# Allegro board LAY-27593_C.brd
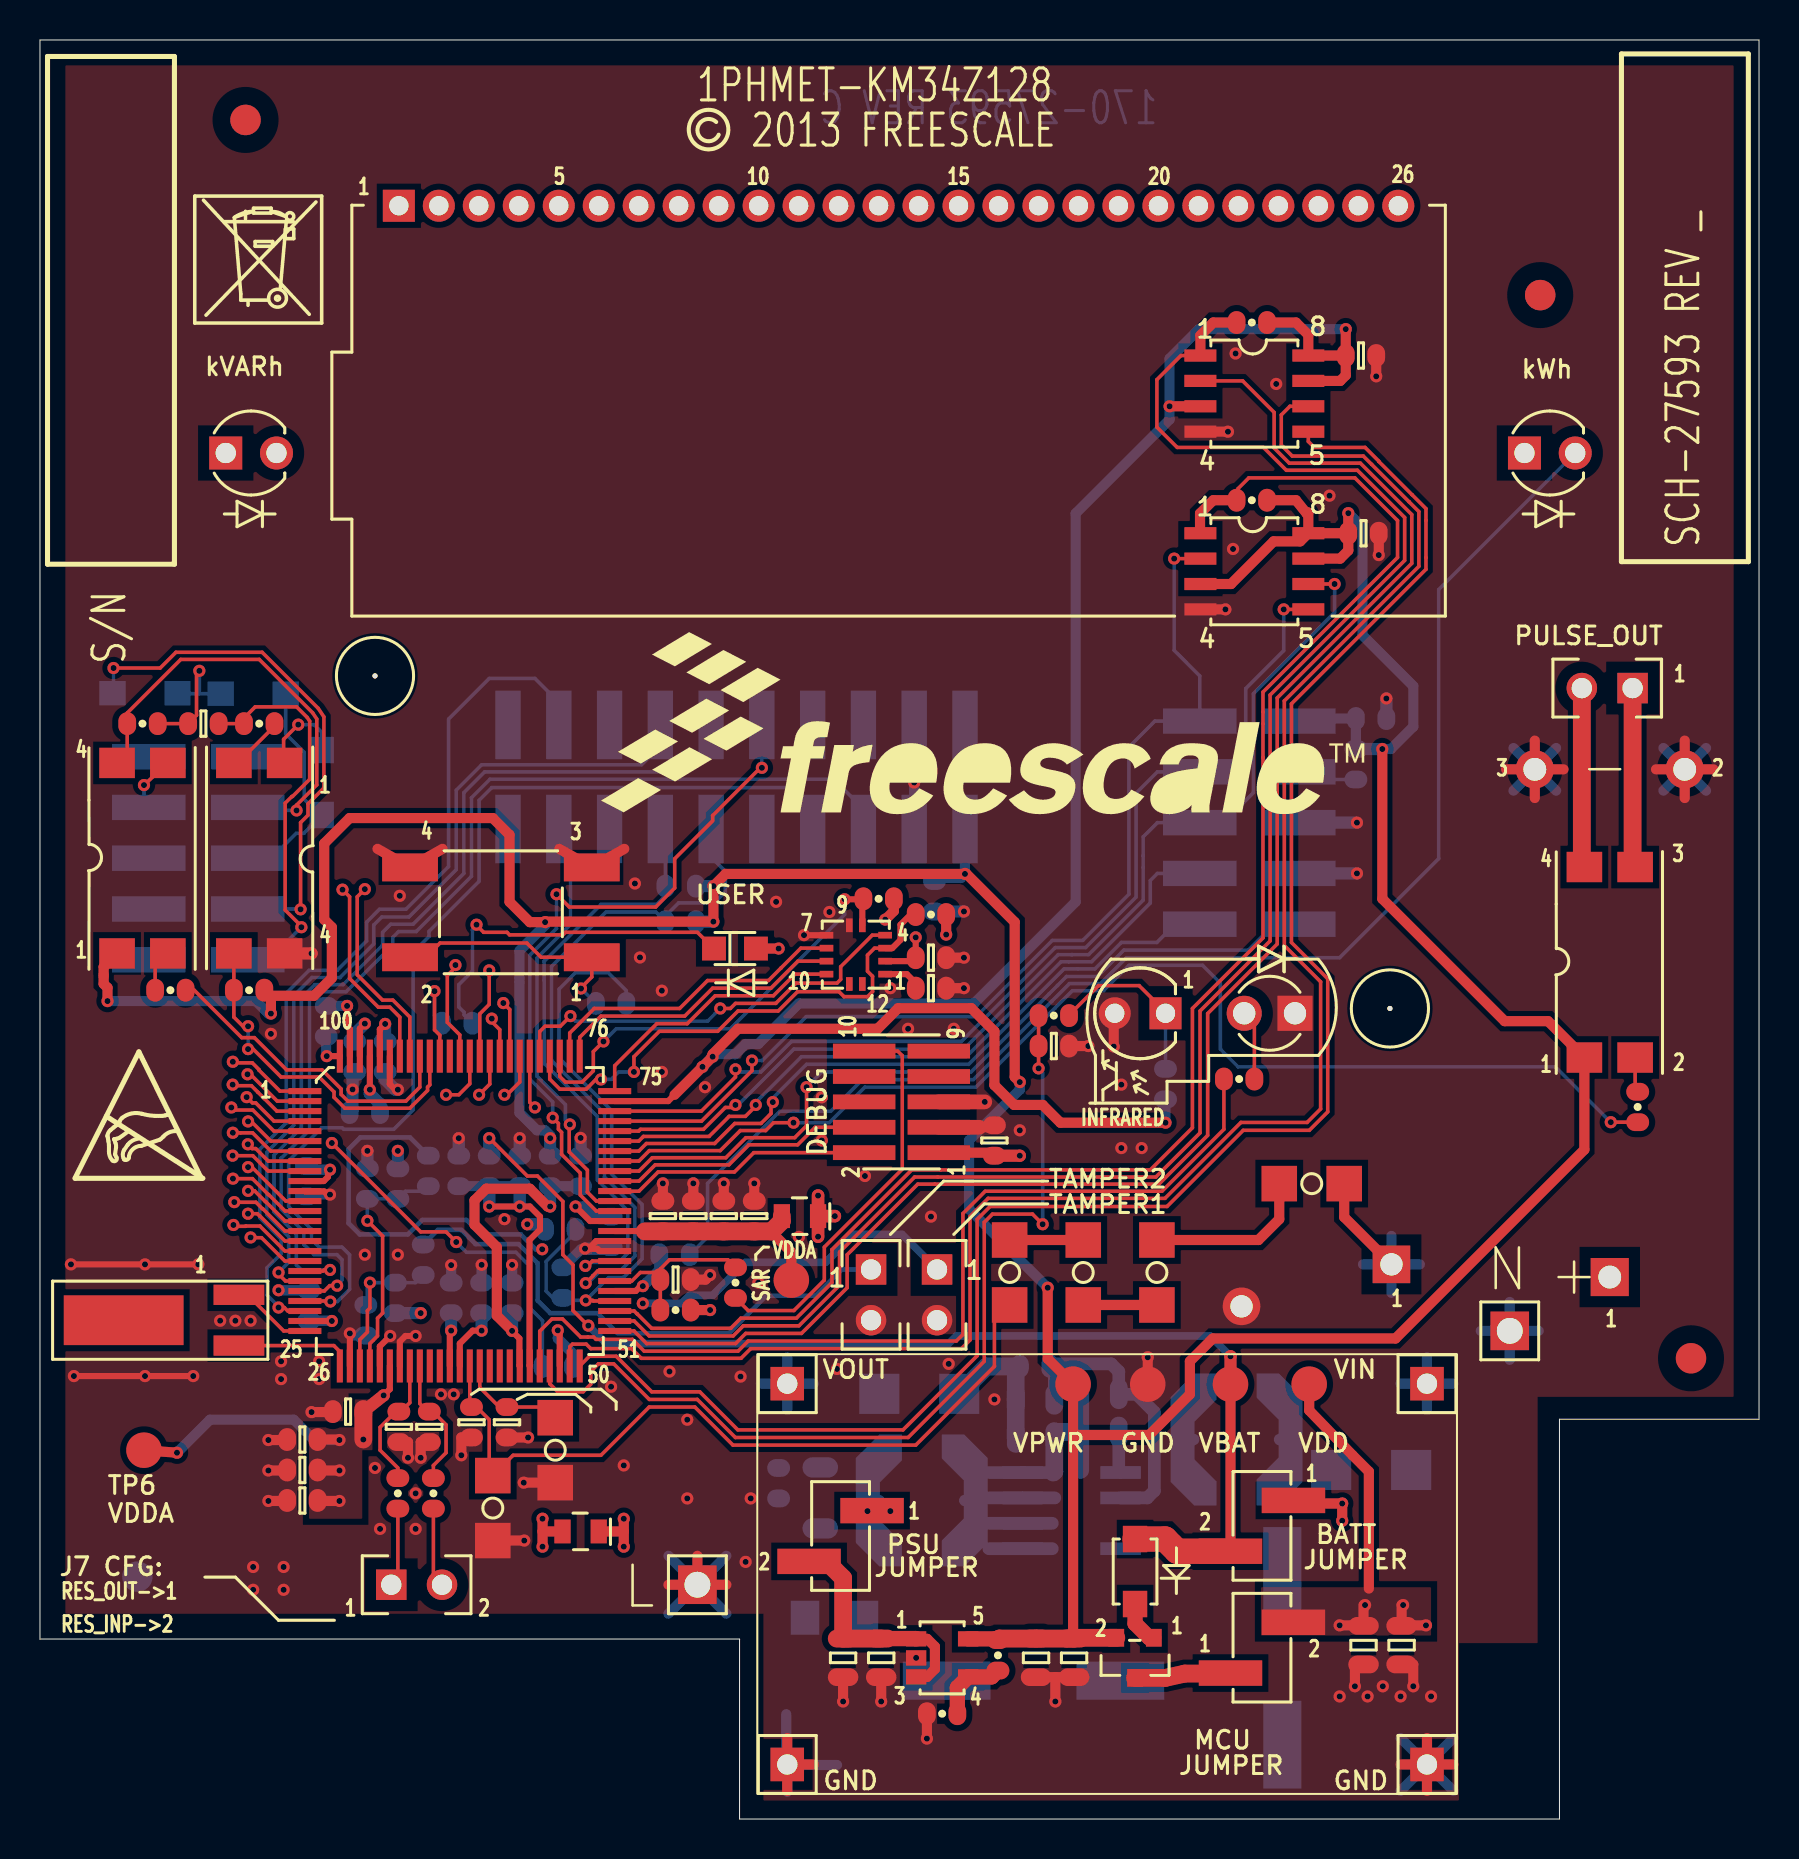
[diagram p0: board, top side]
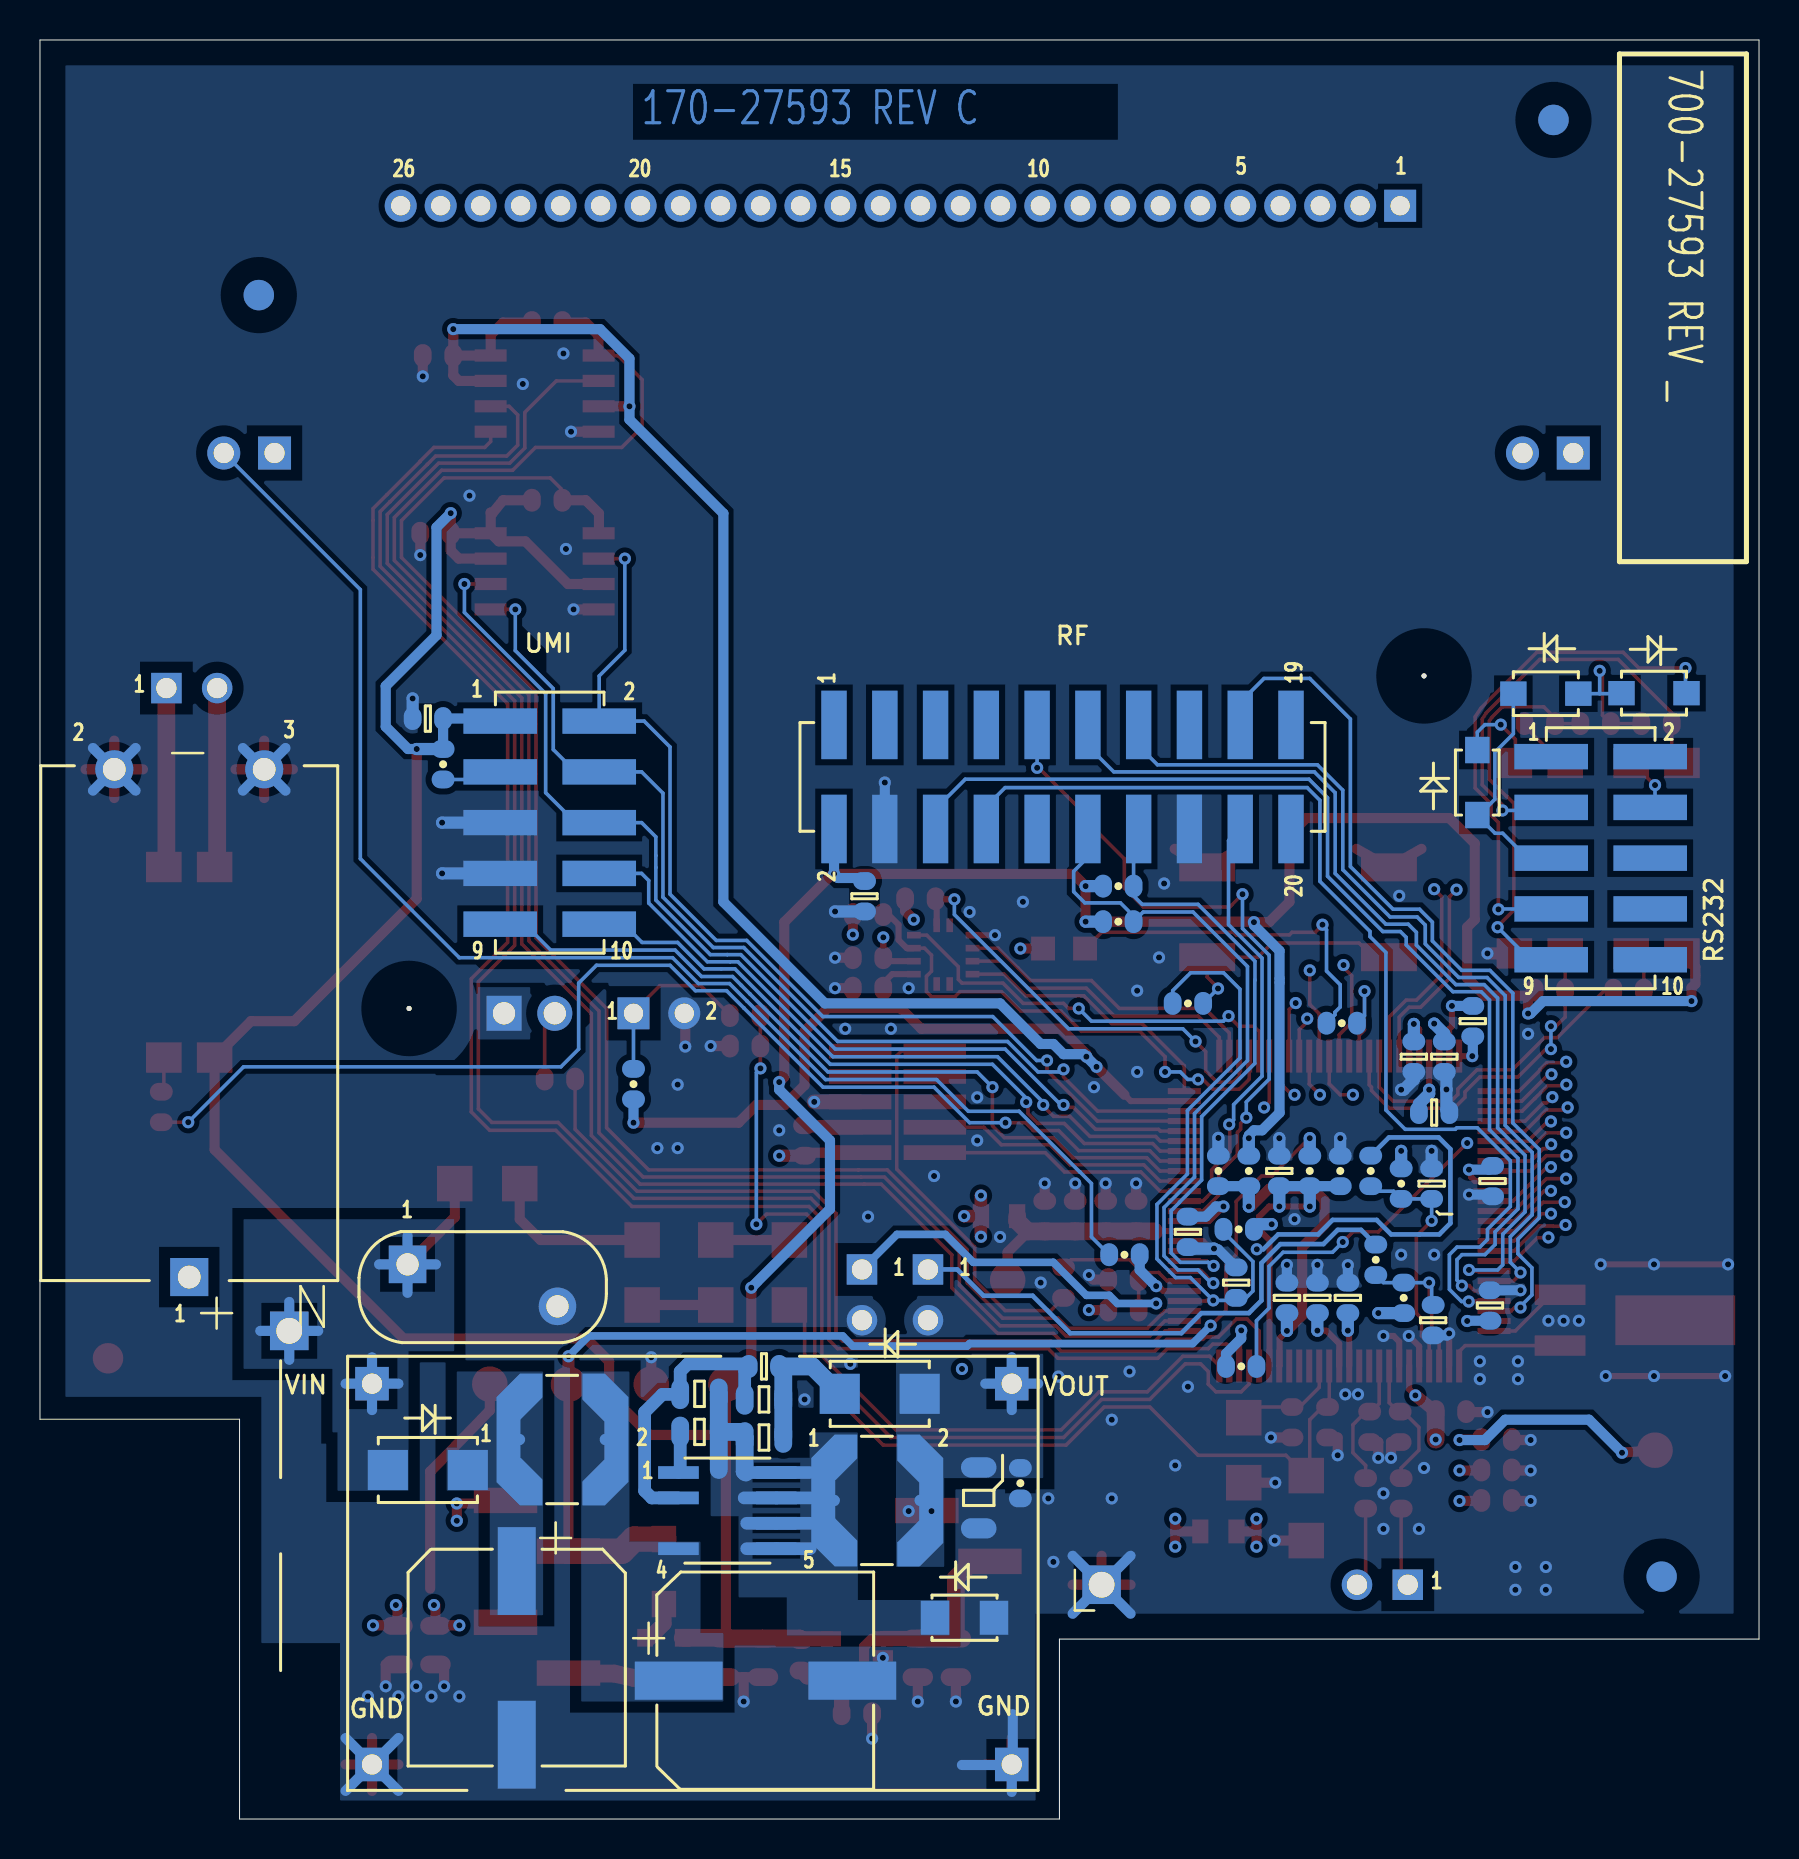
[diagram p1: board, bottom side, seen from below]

Outline 86 x 89 mm; copper layers: TOP, L2_GND, L3_PWR, BOTTOM. Coordinates in mm from the lower left corner of the outline.
Outline path: 0,89 86,89 86,20 76.02,20 76.02,0 35,0 35,9 0,9 0,89

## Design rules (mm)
net group PWR: nets KVARH_LED KWH_LED N7676044 N7742135 N7743508 N7798929 N7799438 N7845653 N7881250 PWR_MSR SAR_VDDA VBAT VBAT_MSR VCAP1 VCAP2 VLL1 VLL2 VLL3 VPWR VREF VREFH VREFL

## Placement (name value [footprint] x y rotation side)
BT200  ER142503PT  [BT25P4_14P5_TH]  78.53 27.11 90 bottom
C1  0.1UF  [CC0603_OV]  66.09 73.21 0 top
C2  0.1UF  [CC0603_OV]  66.21 64.32 0 top
C3  2.2uF  [CC0603_OV]  8.17 54.8 180 top
C4  0.1UF  [CC0603_OV]  44.57 43.09 0 top
C5  0.1UF  [CC0603_OV]  44.57 41.57 0 top
C6  2200PF  [CC0603_OV]  50.72 38.67 0 top
C7  0.1UF  [CC0603_OV]  47.75 33.95 90 top
C8  0.1UF  [CC0603_OV]  31.16 30.16 90 top
C9  1uF  [CC0603_OV]  32.69 30.16 90 top
C10  1uF  [CC0603_OV]  34.21 30.16 90 top
C11  1uF  [CC0603_OV]  35.73 30.16 90 top
C12  0.1UF  [CC0603_OV]  31.8 26.99 0 top
C13  0.1UF  [CC0603_OV]  15.41 20.38 180 top
C14  0.015 UF  [CC0603_OV]  21.59 19.85 270 top
C15  0.015 UF  [CC0603_OV]  23.36 19.85 270 top
C16  0.1UF  [CC0603_OV]  17.95 19.62 270 top
C17  0.1UF  [CC0603_OV]  19.48 19.62 270 top
C18  1uF  [CC0603_OV]  13.13 18.99 180 top
C19  1uF  [CC0603_OV]  13.13 17.46 180 top
C20  1uF  [CC0603_OV]  13.13 15.94 180 top
C21  10UF  [CC0805_OV]  66.21 8.7 270 top
C22  10UF  [CC0805_OV]  68.12 8.7 270 top
C23  10UF  [CC0805_OV]  40.18 8.06 270 top
C24  10UF  [CC0805_OV]  42.08 8.06 270 top
C25  10UF  [CC0805_OV]  49.83 8.06 270 top
C26  10UF  [CC0805_OV]  51.74 8.06 270 top
C200  0.1UF  [CC0603_OV]  66.59 55.05 0 bottom
C201  0.1UF  [CC0603_OV]  44.75 46.16 270 bottom
C202  0.1UF  [CC0603_OV]  14.32 39.91 90 bottom
C203  0.1UF  [CC0603_OV]  17.27 38.14 270 bottom
C204  0.1UF  [CC0603_OV]  15.74 38.14 270 bottom
C205  0.1UF  [CC0603_OV]  16.25 35.34 180 bottom
C206  0.1UF  [CC0603_OV]  24 32.42 90 bottom
C207  0.1UF  [CC0603_OV]  13.33 31.91 270 bottom
C208  2200PF  [CC0603_OV]  16.38 31.79 90 bottom
C209  0.1UF  [CC0603_OV]  28.57 29.37 270 bottom
C210  0.1UF  [CC0603_OV]  26.16 26.83 90 bottom
C211  0.1UF  [CC0603_OV]  23.62 26.07 90 bottom
C212  0.1UF  [CC0603_OV]  22.09 26.07 90 bottom
C213  0.1UF  [CC0603_OV]  20.57 26.07 90 bottom
C214  0.1UF  [CC0603_OV]  13.46 25.69 90 bottom
C215  2200PF  [CC0603_OV]  16.3 24.95 270 bottom
C216  4.7uF  [CC0603_OV]  49.78 22.64 0 bottom
C217  0.1uF  [CC0805_OV]  53.01 19.37 180 bottom
C218  10uF  [CC0805_OV]  49.78 19.09 0 bottom
C219  100UF  [CC1206_OV]  39.04 16.06 270 bottom
C220  4.7uF  [CCE10_3X10_3]  62.15 8.06 270 bottom
C221  4.7uF  [CCE10_3X10_3]  49.7 6.92 180 bottom
D1  WP7104LSRD  [LED_2_3P85]  9.29 68.34 0 top
D2  WP7104LSRD  [LED_2_3P85]  74.27 68.34 0 top
D3  HSMS-C170  [HSMX-C170]  34.77 43.55 180 top
D4  TSAL4400  [LED2_100_3_TH]  62.78 40.31 180 top
D5  MMSD4148T1G  [SOD-123]  54.78 12.38 270 top
D6  BAT54CLT1  [SOT23_A]  54.78 8.06 180 top
D200  MMSD4148T1G  [SOD-123]  5.25 56.32 180 bottom
D201  MMSD4148T1G  [SOD-123]  10.66 56.3 0 bottom
D202  MMSD4148T1G  [SOD-123]  14.09 51.85 90 bottom
D203  MRA4007T3G  [CASE403D_02]  43.99 21.27 180 bottom
D204  MRA4007T3G  [CASE403D_02]  66.59 17.46 0 bottom
D205  ES1JL  [DIODE2_2P9X1P9]  39.75 10.07 180 bottom
DS1  LCD MODULE  [LCD26_2MM_54P15X20MM_TH]  17.95 80.71 0 top
J1  HDR 1X2  [HDR102]  79.68 56.58 270 top
J2  HDR 2X5  [CON_2X5_FTS_SM]  43.1 35.88 90 top
J3  HDR 1X2  [HDR102]  41.58 27.49 0 top
J4  HDR 1X2  [HDR102]  44.88 27.49 0 top
J5  HDR_1X2  [HDR102_STAG_SM]  61.13 14.67 180 top
J6  HDR_1X2  [HDR102_STAG_SM]  40.05 14.16 180 top
J7  HDR 1X2  [HDR102]  17.57 11.72 90 top
J8  HDR_1X2  [HDR102_STAG_SM]  61.13 8.57 0 top
J200  CON_2X10  [CON2X10F_SMT_SSW]  34.84 52.13 90 bottom
J201  HDR_2X5  [HDR205_SM]  60.5 49.85 180 bottom
J202  HDR_2X5  [HDR205_SM]  7.92 48.07 180 bottom
JP1  HDR 1X1  [HDR101]  37.38 21.78 0 top
JP2  HDR 1X1  [HDR101]  69.39 21.78 0 top
JP3  HDR 1X1  [HDR101]  32.89 11.72 0 top
JP4  HDR 1X1  [HDR101]  37.38 2.73 180 top
JP5  HDR 1X1  [HDR101]  69.39 2.73 0 top
JP6  HDR 1X1  [HDR101]  73.53 24.42 0 top
L1  1uH  [IND_2012]  38.02 30.16 180 top
L2  1uH  [IND_2012]  27.05 14.39 180 top
L200  1500uH  [IND_LPS6225]  59.86 18.99 180 bottom
L201  820uH  [IND_LPS6225]  44.12 15.94 180 bottom
NOREF  -  []  76.02 0 0 top
NOREF#2  -  [unnamed#2]  10.28 85 0 top
NOREF#3  -  []  16.76 57.19 0 top
NOREF#4  -  []  -309.96 -251.52 0 top
NOREF#5  -  []  85.47 62.9 90 top
NOREF#6  -  [unnamed#2]  67.53 40.55 0 top
NOREF#7  -  []  86 20 0 top
NOREF#8  -  []  284.4 -45.78 0 top
NOREF#9  -  []  1.77 32.05 0 top
NOREF#10  -  []  -285.83 274.26 0 top
NOREF#11  -  []  6.73 62.77 90 top
NOREF#12  -  [unnamed#2]  75.05 76.24 0 top
NOREF#13  -  []  7.74 74.84 0 top
NOREF#14  -  []  86 89 0 top
NOREF#15  -  []  33.45 52.39 0 top
NOREF#16  -  []  67.53 40.55 0 top
NOREF#17  -  [unnamed#2]  82.6 23.05 0 top
NOREF#18  -  []  35 0 0 top
NOREF#19  -  []  0 89 0 top
NOREF#20  -  []  35 0 0 top
NOREF#21  -  []  86 89 0 top
NOREF#22  -  []  76.83 85.25 0 top
NOREF#23  -  []  -8.08 -35.62 0 top
NOREF#24  -  []  16.76 57.19 0 top
NOREF#25  -  []  0 9 0 top
NOREF#26  -  []  28.06 50.96 0 top
NOREF#27  -  []  16.76 57.19 0 top
NOREF#28  -  [unnamed#2]  16.76 57.19 0 top
NOREF#29  -  []  67.53 40.55 0 top
NOREF#30  -  []  77.09 83.73 180 bottom
NOREF#31  -  [unnamed#2]  10.28 85 180 bottom
NOREF#32  -  []  6.98 88.3 270 bottom
NOREF#33  -  [unnamed#2]  4.87 12.13 180 bottom
NOREF#34  -  [unnamed#2]  75.05 76.24 180 bottom
Q1  OP506B  [PHTRANS_4P19MM]  56.31 40.31 180 top
R1  10K  [RC0603_OV]  60.63 74.87 180 top
R2  10K  [RC0603_OV]  60.63 65.98 180 top
R3  4.7K  [RC0603_OV]  5.13 54.8 0 top
R4  470  [RC0603_OV]  10.97 54.8 180 top
R5  4.7K  [RC0603_OV]  41.96 46.04 180 top
R6  4.7K  [RC0603_OV]  44.57 45.25 180 top
R7  390.0  [RC0603_OV]  6.52 41.46 180 top
R8  1.0K  [RC0603_OV]  10.46 41.46 180 top
R9  1.0K  [RC0603_OV]  50.72 40.19 0 top
R10  680  [RC0603_OV]  59.99 37.02 0 top
R11  390.0  [RC0603_OV]  79.93 35.62 90 top
R12  150K  [RC_MELF_0204]  63.62 31.79 180 top
R13  150K  [RC_MELF_0204]  48.51 27.34 270 top
R14  150K  [RC_MELF_0204]  52.19 27.34 90 top
R15  150K  [RC_MELF_0204]  55.88 27.34 270 top
R16  820  [RC0603_OV]  34.79 26.83 90 top
R17  4.7K  [RC0603_OV]  31.8 25.46 180 top
R18  390  [RC_MELF_0204]  25.78 18.45 270 top
R19  22  [RC0603_OV]  17.9 16.29 90 top
R20  22  [RC0603_OV]  19.68 16.29 90 top
R21  390  [RC_MELF_0204]  22.65 15.56 270 top
R23  45.3K  [RC0603_OV]  47.93 8.19 270 top
R24  23.7K  [RC0603_OV]  45.13 5.27 180 top
R200  0  [RC0603_OV]  65.83 52.77 270 bottom
R201  4.7K  [RC0603_OV]  32.05 46.67 180 bottom
R202  4.7K  [RC0603_OV]  32.05 44.89 180 bottom
R203  10K  [RC0603_OV]  28.57 40.8 180 bottom
R204  2.0K  [RC0603_OV]  20.87 39.81 0 bottom
R205  10K  [RC0603_OV]  56.31 36.77 90 bottom
R206  330K  [RC0603_OV]  27.05 32.42 90 bottom
R207  47K  [RC0603_OV]  25.52 32.42 270 bottom
R208  4.7M  [RC0603_OV]  22.48 32.42 270 bottom
R209  1.6M  [RC0603_OV]  20.95 32.42 90 bottom
R210  10K  [RC0603_OV]  19.43 32.42 90 bottom
R211  4.7M  [RC0603_OV]  17.9 31.79 270 bottom
R212  330K  [RC0603_OV]  26.03 29.5 0 bottom
R213  390.0  [RC0603_OV]  31.75 28.23 0 bottom
R214  10K  [RC0603_OV]  19.17 27.98 90 bottom
R215  4.7M  [RC0603_OV]  17.78 26.07 90 bottom
R216  390.0  [RC0603_OV]  25.9 22.64 180 bottom
R217  2.0K  [RC0805_OV]  53.01 21.27 180 bottom
R218  3.0K  [RC0805_OV]  49.78 20.99 0 bottom
R219  1.6K  [RC0603_OV]  36.95 16.8 270 bottom
RV200  S10K250E2  [VARISTOR_12X5P2MM]  67.61 27.75 180 bottom
SW1  TL3301AF160QG  [SW4_PB_ESW_SM_P177]  23.06 45.36 270 top
TP1  70 MIL  [TESTPOINT_70MIL]  37.59 26.96 0 top
TP2  70 MIL  [TESTPOINT_70MIL]  51.69 21.75 0 top
TP3  70 MIL  [TESTPOINT_70MIL]  55.42 21.75 0 top
TP4  70 MIL  [TESTPOINT_70MIL]  59.56 21.75 0 top
TP5  70 MIL  [TESTPOINT_70MIL]  63.5 21.75 0 top
TP6  70 MIL  [TESTPOINT_70MIL]  5.2 18.45 0 top
U1  CAT25040VE  [SO8_1P27_4X5]  60.75 71.31 0 top
U2  W25X10CLSN  [SO8_1P27_4X5]  60.75 62.42 0 top
U3  SFH6106-4  [SOP4_2P54_6P8X4P8]  10.97 48.07 270 top
U4  SFH6106-4  [SOP4_2P54_6P8X4P8]  5.13 48.07 90 top
U5  MMA8491Q  [QFN12_0P65_3X3_A]  40.81 43.24 180 top
U6  SFH6106-4  [SOP4_2P54_6P8X4P8]  78.53 42.86 90 top
U7  PKM34Z128CLL5  [LQFP100_0P5_14X14]  21 30.42 0 top
U8  SPX3819M5-L  [SOT23-5_A]  45.13 8.06 0 top
U200  LNK302DN  [SO8_1P27_3P9X4P9]  51.61 15.43 180 bottom
Y1  32.768KHz  [XTL2_ECS_SM]  5.38 24.95 0 top

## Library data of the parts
BT200 = BAT_ER142503PT
C1-C5 C7-C13 C16-C26 C200-C207 C209-C214 C216 = CAP_NP: tolerance: 10%
C6 C14 C15 C208 C215 = CAP_NP: tolerance: 5%
C217 C218 = CAP_NP
C219 = CAP_NP: tolerance: 20%
C220 C221 = CAP_POL: tolerance: 20%
D1-D4 = LED
D5 D200-D205 = DIODE
D6 = DUALDIODE_CC_SOT23
DS1 = LCD_MODULE_26P
J1 J3-J8 = CONN_HDR_2X1
J2 J201 J202 = CONN_HDR_5X2
J200 = CONN_HDR_10X2
JP1-JP6 = CONN_HDR_1X1
L1 L2 = INDUCTOR: tolerance: 25%
L200 L201 = IND: tolerance: 20%
Q1 = PT12_PHTRANS_2P
R1-R3 R5 R6 R10 R16 R17 R201-R205 R207 R210 R214 = RES: tolerance: 5%
R4 R7-R9 R11-R15 R19 R20 R23 R24 R200 R206 R208 R209 R211-R213 R215-R219 = RES: tolerance: 1%
R18 R21 = RES: tolerance: 0.1%
RV200 = VARISTOR
SW1 = SW_PB_ESW
TP1-TP6 = Test pad: User Part Number: 510-75218; Tolerance: TOLERANCE
U1 = CAT25040VE_8P
U2 = W25X10C_8P
U3 U4 U6 = SFH6106_4P
U5 = PMA8491_QFN_12P_EPX
U7 = PKM34Z128_LQFP_100P
U8 = SPX3819M5_5P
U200 = LNK302DN_8P
Y1 = XTAL

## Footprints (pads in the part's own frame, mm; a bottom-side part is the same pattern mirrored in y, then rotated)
BT25P4_14P5_TH
  rect 1.905x1.905 hole 1.143: 1(0,0)
  round 1.905 hole 1.143: 2(25.4,3.75) 3(25.4,-3.75)
CASE403D_02
  rect 2.007x2.007 smd: A(2,0) C(-2,0)
CC0603_OV
  oval 0.889x1.143 smd: 1(-0.762,0) 2(0.762,0)
CC0805_OV
  oval 0.889x1.524 smd: 1(-0.965,0) 2(0.965,0)
CC1206_OV
  oval 1.016x1.778 smd: 1(-1.524,0) 2(1.524,0)
CCE10_3X10_3
  rect 4.394x1.905 smd: 1(-4.343,0) 2(4.343,0)
CON2X10F_SMT_SSW
  rect 3.429x1.27 smd: 1(2.603,11.43) 2(-2.603,11.43) 3(2.603,8.89) 4(-2.603,8.89) 5(2.603,6.35) 6(-2.603,6.35) 7(2.603,3.81) 8(-2.603,3.81) 9(2.603,1.27) 10(-2.603,1.27) 11(2.603,-1.27) 12(-2.603,-1.27) 13(2.603,-3.81) 14(-2.603,-3.81) 15(2.603,-6.35) 16(-2.603,-6.35) 17(2.603,-8.89) 18(-2.603,-8.89) 19(2.603,-11.43) 20(-2.603,-11.43)
CON_2X5_FTS_SM
  rect 0.737x3.124 smd: 1(-2.54,-1.867) 2(-2.54,1.867) 3(-1.27,-1.867) 4(-1.27,1.867) 5(0,-1.867) 6(0,1.867) 7(1.27,-1.867) 8(1.27,1.867) 9(2.54,-1.867) 10(2.54,1.867)
DIODE2_2P9X1P9
  rect 1.422x1.702 smd: A(1.475,0) C(-1.475,0)
HDR101
  rect 1.93x1.93 hole 1.295: 1(0,0)
HDR102
  rect 1.524x1.524 hole 1.016: 1(0,0)
  round 1.524 hole 1.016: 2(0,-2.54)
HDR102_STAG_SM
  rect 3.175x1.27 smd: 1(-1.575,-1.27) 2(1.575,1.27)
HDR205_SM
  rect 3.683x1.27 smd: 1(-2.477,5.08) 2(2.477,5.08) 3(-2.477,2.54) 4(2.477,2.54) 5(-2.477,0) 6(2.477,0) 7(-2.477,-2.54) 8(2.477,-2.54) 9(-2.477,-5.08) 10(2.477,-5.08)
HSMX-C170
  rect 1.194x1.194 smd: A(-1.05,0) C(1.05,0)
IND_2012
  rect 0.813x1.194 smd: 1(-0.906,0) 2(0.906,0)
IND_LPS6225
  custom 0.575x0.575 smd: 1(-2.15,0) 2(2.15,0)
LCD26_2MM_54P15X20MM_TH
  rect 1.6x1.6 hole 0.965: 1(0,0)
  round 1.6 hole 0.965: 2(2,0) 3(4,0) 4(6,0) 5(8,0) 6(10,0) 7(12,0) 8(14,0) 9(16,0) 10(18,0) 11(20,0) 12(22,0) 13(24,0) 14(26,0) 15(28,0) 16(30,0) 17(32,0) 18(34,0) 19(36,0) 20(38,0) 21(40,0) 22(42,0) 23(44,0) 24(46,0) 25(48,0) 26(50,0)
LED2_100_3_TH
  round 1.753 hole 1.118: A(2.54,0)
  rect 1.753x1.753 hole 1.118: C(0,0)
LED_2_3P85
  rect 1.651x1.651 hole 1.016: A(0,0)
  round 1.651 hole 1.016: C(2.54,0)
LQFP100_0P5_14X14
  rect 1.651x0.305 smd: 1(-7.75,6) 2(-7.75,5.5) 3(-7.75,5) 4(-7.75,4.5) 5(-7.75,4) 6(-7.75,3.5) 7(-7.75,3) 8(-7.75,2.5) 9(-7.75,2) 10(-7.75,1.5) 11(-7.75,1) 12(-7.75,0.5) 13(-7.75,0) 14(-7.75,-0.5) 15(-7.75,-1) 16(-7.75,-1.5) 17(-7.75,-2) 18(-7.75,-2.5) 19(-7.75,-3) 20(-7.75,-3.5) 21(-7.75,-4) 22(-7.75,-4.5) 23(-7.75,-5) 24(-7.75,-5.5) 25(-7.75,-6) 51(7.75,-6) 52(7.75,-5.5) 53(7.75,-5) 54(7.75,-4.5) 55(7.75,-4) 56(7.75,-3.5) 57(7.75,-3) 58(7.75,-2.5) 59(7.75,-2) 60(7.75,-1.5) 61(7.75,-1) 62(7.75,-0.5) 63(7.75,0) 64(7.75,0.5) 65(7.75,1) 66(7.75,1.5) 67(7.75,2) 68(7.75,2.5) 69(7.75,3) 70(7.75,3.5) 71(7.75,4) 72(7.75,4.5) 73(7.75,5) 74(7.75,5.5) 75(7.75,6)
  rect 0.305x1.651 smd: 26(-6,-7.75) 27(-5.5,-7.75) 28(-5,-7.75) 29(-4.5,-7.75) 30(-4,-7.75) 31(-3.5,-7.75) 32(-3,-7.75) 33(-2.5,-7.75) 34(-2,-7.75) 35(-1.5,-7.75) 36(-1,-7.75) 37(-0.5,-7.75) 38(0,-7.75) 39(0.5,-7.75) 40(1,-7.75) 41(1.5,-7.75) 42(2,-7.75) 43(2.5,-7.75) 44(3,-7.75) 45(3.5,-7.75) 46(4,-7.75) 47(4.5,-7.75) 48(5,-7.75) 49(5.5,-7.75) 50(6,-7.75) 76(6,7.75) 77(5.5,7.75) 78(5,7.75) 79(4.5,7.75) 80(4,7.75) 81(3.5,7.75) 82(3,7.75) 83(2.5,7.75) 84(2,7.75) 85(1.5,7.75) 86(1,7.75) 87(0.5,7.75) 88(0,7.75) 89(-0.5,7.75) 90(-1,7.75) 91(-1.5,7.75) 92(-2,7.75) 93(-2.5,7.75) 94(-3,7.75) 95(-3.5,7.75) 96(-4,7.75) 97(-4.5,7.75) 98(-5,7.75) 99(-5.5,7.75) 100(-6,7.75)
PHTRANS_4P19MM
  rect 1.6x1.6 hole 0.965: 1(0,0)
  round 1.6 hole 0.965: 2(2.54,0)
QFN12_0P65_3X3_A
  rect 0.686x0.33 smd: 1(-1.468,0.975) 2(-1.468,0.325) 3(-1.468,-0.325) 4(-1.468,-0.975) 7(1.468,-0.975) 8(1.468,-0.325) 9(1.468,0.325) 10(1.468,0.975)
  rect 0.33x0.686 smd: 5(-0.325,-1.468) 6(0.325,-1.468) 11(0.325,1.468) 12(-0.325,1.468)
RC0603_OV
  oval 0.889x1.143 smd: 1(-0.762,0) 2(0.762,0)
RC0805_OV
  oval 0.889x1.524 smd: 1(-0.965,0) 2(0.965,0)
RC_MELF_0204
  rect 1.778x1.778 smd: 1(-1.625,0) 2(1.625,0)
SO8_1P27_3P9X4P9
  rect 2.032x0.635 smd: 1(-2.45,1.905) 2(-2.45,0.635) 4(-2.45,-1.905) 5(2.45,-1.905) 6(2.45,-0.635) 7(2.45,0.635) 8(2.45,1.905)
SO8_1P27_4X5
  rect 1.6x0.61 smd: 1(-2.7,1.905) 2(-2.7,0.635) 3(-2.7,-0.635) 4(-2.7,-1.905) 5(2.7,-1.905) 6(2.7,-0.635) 7(2.7,0.635) 8(2.7,1.905)
SOD-123
  rect 1.321x1.219 smd: A(-1.626,0) C(1.626,0)
SOP4_2P54_6P8X4P8
  rect 1.52x1.78 smd: 1(-4.765,1.27) 2(-4.765,-1.27) 3(4.765,-1.27) 4(4.765,1.27)
SOT23-5_A
  rect 1.016x0.762 smd: 1(-1.3,0.95) 2(-1.3,0) 3(-1.3,-0.95) 4(1.3,-0.95) 5(1.3,0.95)
SOT23_A
  rect 0.787x0.889 smd: 1(-0.94,-1.003) 2(0.94,-1.003) 3(0,1.003)
SW4_PB_ESW_SM_P177
  rect 1.397x2.794 smd: 1(2.248,4.547) 2(2.248,-4.547) 3(-2.248,4.547) 4(-2.248,-4.547)
TESTPOINT_70MIL
  round 1.778 smd: 1(0,0)
unnamed#2
  round 1.524 smd: (0,0)
VARISTOR_12X5P2MM
  rect 1.88x1.88 hole 1.118: 1(0,0)
  round 1.88 hole 1.118: 2(7.5,-2.1)
XTL2_ECS_SM
  rect 5.994x2.489 smd: (-1.194,0)
  rect 2.54x1.016 smd: 1(4.572,1.27) 2(4.572,-1.27)

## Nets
GND: BT200.2(-VE1) BT200.3(-VE2) C1.2 C2.2 C4.2 C5.2 C6.2 C7.2 C8.2 C9.2 C10.2 C11.2 C12.2 C13.2 C14.2 C15.2 C16.2 C17.2 C18.2 C19.2 C20.2 C21.2 C22.2 C23.2 C24.2 C25.2 C26.2 C200.2 C201.2 C203.2 C204.2 C205.2 C206.2 C207.2 C208.2 C209.2 C210.2 C211.2 C212.2 C213.2 C214.2 C215.2 C219.2 C220.2 C221.2 D4.C(CATHODE) D205.A(ANODE) J2.3(A2) J2.5(A3) J3.2 J4.2 J200.4 J200.16 J201.5(A3) J201.7(A4) JP3.1 JP4.1 JP5.1 Q1.2(EMITTER) R18.2 R21.2 R24.2 R206.2 R209.2 R219.2 RV200.2 SW1.3(B1) SW1.4(B2) TP3.1(PIN1) U1.4(VSS) U2.4(GND) U3.4(EMITTER) U5.6(GND#6) U5.7(GND#7) U7.11(VSS1) U7.27(VSS2) U7.30(TAMPER0) U7.32(VSSA) U7.59(VSS3) U7.60(SAR_VSSA) U7.95(VSS4) U8.2(GND)
VBAT: D5.A(ANODE) J5.2 R208.1 TP4.1(PIN1)
VBAT_MSR: C206.1 R208.2 R209.1 U7.45(PTC6/AD1/SCI0_CTS/QT1)
VDD: C4.1 C7.1 C21.1 C22.1 C207.1 C209.1 C214.1 D1.A(ANODE) D2.A(ANODE) D3.A(ANODE) J2.1(A1) J8.2 L1.1 L2.1 R5.1 R6.1 R17.1 R211.1 R212.1 R215.1 TP5.1(PIN1) U5.2(VDD) U7.10(VDD1) U7.24(VBAT) U7.62(VDD2)
VDDA: C13.1 C18.1 C19.1 C20.1 L2.2 TP6.1(PIN1) U7.31(VDDA)
VIN: D204.A(ANODE) JP2.1 JP6.1 R12.1 RV200.1
/PULSE_OUT: R11.1 U7.68(PTF1/LCD0/AD8/QT0/PXBAR_OUT6)
/RESET: C12.1 R16.2 R17.2 U7.56(PTE1/R\E\S\E\T\)
COM1: DS1.23 U7.84(PTH1/LCD16)
COM2: DS1.24 U7.83(PTH0/LCD15)
COM3: DS1.25 U7.82(PTG7/LCD14)
COM4: DS1.26 U7.81(PTG6/LCD13/LLWU_P0/LPTIM2)
EEPROM_SS: R1.2 U1.1(C\S\) U7.52(PTD5/AD4/LPTIM2/QT0/SCI3_CTS)
FLASH_SS: R2.2 U2.1(C\S\) U7.53(PTD6/AD5/LPTIM1/CMP1OUT/SCI3_RT)
I2C0_SCL: R5.2 U5.5(SCL) U7.78(PTG3/LCD10/SPI0_SCK/I2C0_SCL)
I2C0_SDA: R6.2 U5.3(SDA) U7.79(PTG4/LCD11/SPI0_MOSI/I2C0_SDA)
I2C1_SCL: J200.14 R201.2 U7.58(PTE3/XTAL1/EWM_OUT/AFE_CLK/I2C1)
I2C1_SDA: J200.12 R202.2 U7.57(PTE2/EXTAL1/EWM_IN/PXBAR_IN6/I2)
KVARH_LED: R216.1 U7.48(PTD1/SCI1_TXD/S\P\I\0\_\S\S\/PX)
KWH_LED: R213.1 U7.55(PTE0/I2C0_SDA/PXBAR_OUT4/SCI3_T)
LCD1: DS1.1 U7.18(PTB7/LCD38/AFE_CLK)
LCD2: DS1.2 U7.17(PTB6/LCD37/CMP1P0)
LCD3: DS1.3 U7.16(PTB5/LCD36)
LCD4: DS1.4 U7.15(PTB4/LCD35)
LCD5: DS1.5 U7.14(PTB3/LCD34)
LCD6: DS1.6 U7.13(PTB2/LCD33)
LCD7: DS1.7 U7.12(PTB1/LCD32)
LCD8: DS1.8 U7.9(PTB0/LCD31)
LCD9: DS1.9 U7.8(PTA7/LCD30/PXBAR_OUT0)
LCD10: DS1.10 U7.7(PTA6/LCD29/PXBAR_IN0/LLWU_P14)
LCD11: DS1.11 U7.6(PTA5/LCD28/CMP0OUT)
LCD12: DS1.12 U7.5(PTA4/LCD27/LLWU_P15/N\M\I\)
LCD13: DS1.13 U7.4(PTA3/LCD26)
LCD14: DS1.14 U7.3(PTA2/LCD25)
LCD15: DS1.15 U7.2(PTA1/LCD24)
LCD16: DS1.16 U7.1(PTA0/LCD23)
LCD17: DS1.17 U7.94(PTI3/LCD22)
LCD18: DS1.18 U7.93(PTI2/LCD21)
LCD19: DS1.19 U7.88(PTH5/LCD20)
LCD20: DS1.20 U7.87(PTH4/LCD19)
LCD21: DS1.21 U7.86(PTH3/LCD18)
LCD22: DS1.22 U7.85(PTH2/LCD17)
MMA_EN: U5.4(EN) U7.80(PTG5/LCD12/SPI0_MISO/LPTIM1)
MMA_XOUT: U5.10(XOUT) U7.75(PTG0/LCD7/QT1/LPTIM2)
MMA_YOUT: U5.9(YOUT) U7.76(PTG1/LCD8/AD10/LLWU_P2/LPTIM0)
MMA_ZOUT: U5.8(ZOUT) U7.77(PTG2/LCD9/AD11/S\P\I\0\_\S\S\/L)
PWR_MSR: C211.1 R206.1 R207.2 U7.44(PTC5/AD0/SCI0_RTS/LLWU_P12)
RES_INP: J7.2 R20.1
RES_OUT: J7.1 R19.1
RF_CTRL: J200.18 U7.64(PTE5/QT3/SCI2_RTS/EWM_OUT/LLWU_)
RF_IO: J200.17 U7.23(PTC4/LCD43)
RF_RST: J200.9 U7.63(PTE4/LPTIM0/SCI2_CTS/EWM_IN)
SAR_VDDA: C8.1 C9.1 C10.1 C11.1 L1.2 TP1.1(PIN1) U7.61(SAR_VDDA)
SCI0_RX: C6.1 R9.1 U7.47(PTD0/CMP0P0/SCI0_RXD/PXBAR_IN2/)
SCI0_TX: R10.1 U7.46(PTC7/AD2/SCI0_TXD/PXBAR_OUT2)
SCI1_RX: R8.2 U3.3(COLLECTOR) U7.91(PTI0/CMP0P5/SCI1_RXD/PXBAR_IN8/)
SCI1_TX: R7.1 U7.92(PTI1/SCI1_TXD/PXBAR_OUT8/SPI1_M)
SCI3_CTS: J200.13 U7.20(PTC1/LCD40/CMP1P1/SCI3_CTS)
SCI3_RTS: J200.11 U7.19(PTC0/LCD39/SCI3_RTS/PXBAR_IN1)
SCI3_RX: J200.8 U7.22(PTC3/LCD42/CMP0P3/SCI3_RXD/LLWU)
SCI3_TX: J200.6 U7.21(PTC2/LCD41/SCI3_TXD/PXBAR_OUT1)
SDADM0: C17.1 R20.2 U7.34(SDADM0)
SDADM2: C15.1 R18.1 U7.40(SDADM2/CMP1P3)
SDADP0: C16.1 R19.2 U7.33(SDADP0)
SDADP2: C14.1 R13.2 R21.1 U7.39(SDADP2/CMP1P2)
SPI0_MISO: U1.2(SO) U7.51(PTD4/AD3/SCI1_RTS/SPI0_MISO/LLW)
SPI0_MOSI: U1.5(SI) U7.50(PTD3/SCI1_CTS/SPI0_MOSI)
SPI0_SCK: U1.6(SCK) U7.49(PTD2/CMP0P1/SCI1_RXD/SPI0_SCK/P)
SPI1_MISO: J201.2(B1) U2.2(DO/IO1) U7.72(PTF5/LCD4/SPI1_MISO/I2C1_SCL/LL)
SPI1_MOSI: J201.4(B2) U2.5(DI/IO0) U7.73(PTF6/LCD5/SPI1_MOSI/I2C1_SDA/LL)
SPI1_SCK: J201.6(B3) U2.6(CLK) U7.71(PTF4/LCD3/SPI1_SCK/LPTIM0/SCI0_)
SWD_CLK: J2.4(B2) U7.66(PTE7/AD6/PXBAR_OUT5/SCI2_TXD/SW)
SWD_IO: J2.2(B1) U7.65(PTE6/CMP0P2/PXBAR_IN5/SCI2_RXD/)
SWD_RESET: J2.10(B5) R16.1
TAMPER1: C208.1 R210.1 R211.2 U7.29(TAMPER1)
TAMPER2: C215.1 R214.1 R215.2 U7.28(TAMPER2)
UMI_INT: J201.9(A5) U7.67(PTF0/AD7/RTCCLKOUT/QT2/CMP0OUT)
UMI_RST: J201.10(B5) U7.69(PTF2/LCD1/AD9/CMP1OUT/RTCCLKOUT)
UMI_SS: J201.8(B4) U7.70(PTF3/LCD2/S\P\I\1\_\S\S\/LPTIM1)
USER_BTN: C210.1 R203.1 R212.2 U7.54(PTD7/CMP0P4/I2C0_SCL/PXBAR_IN4/)
USER_LED: R204.1 U7.90(PTH7/SCI1_RTS/SPI1_SCK/PXBAR_OU)
VAUX: C1.1 R1.1 R205.1 U1.3(W\P\) U1.7(H\O\L\D\) U1.8(VCC) U7.74(PTF7/LCD6/QT2/CLKOUT)
VCAP1: C202.1 U7.100(VCAP1)
VCAP2: C202.2 U7.99(VCAP2)
VLL1: C204.1 U7.98(VLL1)
VLL2: C205.1 U7.97(VLL2)
VLL3: C203.1 U7.96(VLL3)
VOUT: C219.1 D203.A(ANODE) J6.1 JP1.1 L201.2 R219.1
VPWR: C2.1 C25.1 C26.1 C200.1 C201.1 D6.2(A2) J200.2 J201.1(A1) R2.1 R8.1 R23.1 R200.1 R201.1 R202.1 R207.1 TP2.1(PIN1) U2.3(W\P\) U2.7(H\O\L\D\) U2.8(VCC) U4.1(ANODE) U6.1(ANODE) U8.5(VOUT)
VREF: U7.41(VREF)
VREFH: C213.1 U7.37(VREFH)
VREFL: C212.1 U7.38(VREFL)
N7254025: J201.3(A2) R200.2
N7311373: Q1.1(COLLECTOR) R9.2 R205.2
N7313274: D4.A(ANODE) R10.2
N7314056: D2.C(CATHODE) R213.2
N7314060: D1.C(CATHODE) R216.2
N7317031: J1.1 U6.3(COLLECTOR)
N7317123: J202.3(A2) R3.1 U4.4(EMITTER)
N7317135: R4.1 U3.2(CATHODE)
N7317139: C3.2 D200.A(ANODE) D201.A(ANODE) R3.2
N7317159: C3.1 J202.9(A5) R4.2
N7317195: D200.C(CATHODE) J202.7(A4)
N7317203: D201.C(CATHODE) D202.A(ANODE) J202.5(A3)
N7317219: J202.4(B2) U4.3(COLLECTOR)
N7317435: R11.2 U6.2(CATHODE)
N7330976: J1.2 U6.4(EMITTER)
N7332359: R7.2 U4.2(CATHODE)
N7333527: D202.C(CATHODE) U3.1(ANODE)
N7413835: C5.1 U5.1(BYP)
N7432331: R13.1 R14.2
N7432681: R14.1 R15.2
N7432685: R12.2 R15.1
N7470913: C217.2 C218.2 D205.C(CATHODE) L201.1 R217.2 U200.5(S1) U200.6(S2) U200.7(S3) U200.8(S4)
N7471025: C220.1 D204.C(CATHODE) L200.1
N7471045: C221.1 L200.2 U200.4(D)
N7471057: C217.1 U200.1(BP)
N7471061: C216.2 R217.1 R218.2 U200.2(FB)
N7471069: C216.1 C218.1 D203.C(CATHODE) R218.1
N7676044: C23.1 C24.1 J6.2 U8.1(VIN) U8.3(EN)
N7706869: U7.25(XTAL32K) Y1.1
N7742135: D5.C(CATHODE) D6.1(A1)
N7743508: R23.2 R24.1 U8.4(ADJ)
N7798929: J4.1 R210.2
N7799438: J3.1 R214.2
N7817781: U7.26(EXTAL32K) Y1.2
N7845653: D6.3(C) J8.1
N7881250: BT200.1(+VE) J5.1
N8061225: D3.C(CATHODE) R204.2
N8098939: R203.2 SW1.1(A1) SW1.2(A2)

Pads without a net: J2 6 7 8 9; J200 1 3 5 7 10 15 19 20; J202 1 2 6 8 10; U5 11 12; U7 35 36 42 43 89

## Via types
v1: diameter 0.61, hole 0.305, TOP to BOTTOM, 262 vias

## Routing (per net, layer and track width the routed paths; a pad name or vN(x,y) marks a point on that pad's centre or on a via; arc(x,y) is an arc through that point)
GND: length 192.5
  TOP w0.305: v1(17.52,24.17) 17,23.65 U7.30 ; U7.95 17.5,36.76 17.78,36.49 v1(17.9,36.49) ; U7.27 v1(15.5,24.29) ; U7.32 18,23.88 18.28,24.17 v1(18.79,24.17) ; U7.11 13.27,31.4 14.21,31.4 14.37,31.24 v1(14.51,31.24) ; v1(1.55,27.75) v1(5.25,27.75) v1(7.92,27.75) ; U7.59 27.99,28.42 27.88,28.52 27.28,28.52 v1(27.27,28.54) 27.45,28.54 27.83,28.92 U7.60 ; v1(7.67,22.16) v1(5.25,22.16) v1(1.7,22.16) ; U5.7 v1(38.22,44.22)
  TOP w0.508: v1(13.59,20.36) 14.65,20.36 C13.2 ; 50.8,7.1 C26.2 ; 50.8,7.1 C25.2 ; 50.8,7.1 v1(50.8,5.88) ; C9.2 v1(32.69,31.8) ; C8.2 v1(31.16,31.8) ; 46.99,34.61 47.65,34.61 C7.2 ; U1.4 v1(59.43,69.4) ; C1.2 v1(66.85,72.17) ; 80.85,52.51 BT200.2 ; BT200.2 82.28,53.95 ; BT200.2 82.28,51.08 ; BT200.2 83.72,52.51 ; v1(24.2,16.83) R18.2 ; C6.2 v1(52.45,38.67) 52.45,38.64 ; R24.2 v1(44.37,4.02) ; JP5.1 70.71,2.73 ; JP5.1 69.39,4.05 ; JP5.1 69.39,1.41 ; JP5.1 68.07,2.73 ; v1(66.98,63.23) C2.2 ; v1(11.43,17.44) 12.37,17.44 C19.2 ; v1(53.72,38.64) 53.72,40.31 Q1.2 ; v1(11.43,15.91) 12.37,15.91 C20.2 ; v1(33.52,27.21) 33.3,26.99 C12.2 ; v1(65.78,6.64) 65.78,7.73 C21.2 ; v1(68.7,6.64) 68.7,7.73 C22.2 ; 37.38,1.41 JP4.1 ; JP4.1 38.71,2.73 ; JP4.1 37.38,4.05 ; TP3.1 v1(55.42,23.1) ; BT200.3 76.22,52.51 ; BT200.3 74.78,51.08 ; BT200.3 73.35,52.51 ; BT200.3 74.78,53.95 ; C24.2 v1(42.08,5.88) ; v1(18.41,18.07) 18.41,18.86 C16.2 ; v1(24.42,19.09) C15.2 ; C23.2 v1(40.18,5.88) ; U2.4 v1(59.31,60.51) ; v1(19.05,18.07) 19.05,18.86 C17.2 ; JP3.1 32.89,13.17 ; JP3.1 34.34,11.72 ; JP3.1 31.44,11.72 ; C5.2 v1(46.22,41.57) ; 16.89,48.53 SW1.4 20.14,48.53 ; C18.2 12.37,18.96 v1(11.43,18.96) ; C11.2 v1(35.73,31.8) ; 29.23,48.53 SW1.3 25.98,48.53 ; v1(24.23,13.93) R21.2 ; C4.2 v1(46.22,43.09) ; C10.2 v1(34.21,31.8) ; v1(21.08,18.2) 21.08,19.09 C14.2
  TOP w0.61: U3.4 v1(13.59,43.3)
  TOP w0.737: 46.99,34.61 J2.3 ; J2.5 v1(47.27,35.88)
  L2_GND w0.508: 74.78,51.08 BT200.3 ; BT200.3 76.22,52.51 ; BT200.3 73.35,52.51 ; BT200.3 74.78,53.95 ; JP3.1 34.34,11.72 ; JP3.1 32.89,13.17 ; JP3.1 31.44,11.72 ; JP4.1 37.79,2.32 39.62,2.32 ; JP4.1 37.21,2.91 37.21,4.74 ; JP4.1 38.63,3.97 ; 62.78,38.09 D4.C 62.78,42.25 ; 82.28,51.08 BT200.2 ; BT200.2 80.85,52.51 ; BT200.2 82.28,53.95 ; BT200.2 83.72,52.51 ; 68.07,2.73 JP5.1 ; JP5.1 69.39,4.05 ; JP5.1 70.71,2.73
  BOTTOM w0.508: v1(11.93,26.45) C214.2 ; J200.4 v1(43.73,51.85) ; JP3.1 34.34,13.17 ; JP3.1 34.34,10.27 ; JP3.1 31.44,10.27 ; JP3.1 31.44,13.17 ; 81.22,53.58 BT200.2 ; BT200.2 83.35,51.45 ; BT200.2 83.35,53.58 ; BT200.2 81.22,51.45 ; JP5.1 70.71,4.05 ; JP5.1 70.71,1.41 ; JP5.1 68.07,1.41 ; JP5.1 68.07,4.05 ; v1(14.51,31.24) 13.42,31.24 C207.2 ; JP4.1 37.41,2.7 39.87,2.7 ; JP4.1 37.38,1.36 ; JP4.1 37.33,2.78 37.33,5.24 ; 73.72,53.58 BT200.3 ; BT200.3 75.85,51.45 ; BT200.3 75.85,53.58 ; BT200.3 73.72,51.45 ; v1(27.27,28.54) 27.23,28.49 27.06,28.49 C210.2 ; v1(15.5,24.29) 15.6,24.19 C215.2 ; C212.2 v1(22.09,27.72) ; C211.2 v1(23.62,27.72) ; C213.2 v1(20.57,27.71)
  BOTTOM w0.61: C205.2 15.64,35.49 v1(15.64,36.5) 15.64,37.27 C204.2 ; R209.2 v1(20.95,34.06) ; C203.2 17.27,36.99 17.78,36.49 v1(17.9,36.49) ; C200.2 v1(67.36,56.06) ; J201.7 v1(65.88,47.31) ; C209.2 28.49,28.54 v1(27.27,28.54) ; v1(46.22,45.4) C201.2 ; C208.2 v1(16.38,33.42) ; J201.5 v1(65.88,49.85) ; R206.2 v1(27.05,34.07) ; C206.2 v1(24,34.06)
  vias: v1(9.01,24.93) v1(9.78,24.93) v1(10.54,24.93) v1(10.66,12.61) v1(10.66,11.47) v1(11.55,39.28) v1(12.06,22.9) v1(12.06,22.01) v1(12.19,12.61) v1(12.19,11.47) v1(13.97,22.9) v1(13.97,22.01) v1(16.25,28.23) v1(16.76,17.56) v1(17.01,14.51) v1(17.9,28.23) v1(18,46.19) v1(18.79,16.29) v1(18.79,14.51) v1(20.06,21.25) v1(20.7,21.25) v1(23.24,30.01) v1(28.57,21.63) v1(29.21,17.69) v1(29.76,46.8) v1(30.02,43.1) v1(31.11,41.44) v1(31.11,37.37) v1(31.49,22.39) v1(32.38,19.98) v1(32.38,16.04) v1(33.27,36.61) v1(35.05,22.13) v1(35.3,12.86) v1(35.56,16.04) v1(35.94,26.83) v1(36.83,45.88) v1(37.97,29.12) v1(39.11,36.1) v1(39.11,33.95) v1(39.49,45.38) v1(39.87,22.52) v1(41.27,32.17) v1(42.54,41.57) v1(43.43,39.53) v1(43.83,8.06) v1(44.57,30.14) v1(45.46,22.77) v1(45.72,39.53) v1(47.75,20.99) v1(49.02,34.45) v1(54.1,36.74) v1(54.1,33.56) v1(55.11,33.56) v1(59.69,63.54) v1(59.81,73.32) v1(61.85,71.79) v1(64.51,66.2) v1(65.02,6.13) v1(66.42,6.13) v1(67.18,6.64) v1(68.07,6.13) v1(69.59,6.13)
VBAT: length 60.6
  TOP w0.178: v1(22.48,34.06) 22.49,34.06 24.38,32.17 24.89,32.17 26.16,30.9 26.16,28.23 26.67,27.72 26.67,25.44 27.42,24.68 v1(27.43,24.68)
  TOP w0.508: J5.2 TP4.1
  TOP w0.61: TP4.1 v1(59.56,23.15)
  TOP w1.27: D5.A 56.28,14.01 56.89,13.4 J5.2
  BOTTOM w0.381: v1(59.56,23.15) 58.54,24.17 45.84,24.17 45.34,23.66 39.62,23.66 39.49,23.79 28.33,23.79 v1(27.43,24.68)
  BOTTOM w0.61: R208.1 v1(22.48,34.06)
VBAT_MSR: length 15.5
  TOP w0.305: U7.45 24.49,22.68 24.49,28.97 25.02,29.49 25.02,30.14 24.51,30.64 v1(24,30.64) v1(22.48,30.64)
  BOTTOM w0.508: R209.1 R208.2 C206.1
  BOTTOM w0.61: R208.2 v1(22.48,30.64) ; C206.1 v1(24,30.64)
VDD: length 76.9
  TOP w0.305: U7.10 14.2,31.91 14.41,32.13 14.41,32.38 v1(14.51,32.48) ; v1(26.79,30.64) 27.52,29.92 U7.62 ; v1(43.81,44.11) C4.1 43.64,42.92 U5.2 ; U7.24 v1(14.6,24.92)
  TOP w0.508: v1(42.29,44.99) 42.72,45.43 R5.1 ; 68.12,9.69 v1(69.34,9.69) ; 68.12,9.69 68.12,10.7 v1(68.2,10.7) ; 68.12,9.69 C22.1 ; 66.21,9.69 v1(65.02,9.69) ; 66.21,9.69 66.21,10.7 ; 66.21,9.69 C21.1 ; TP5.1 63.5,20.44 65.67,18.2 66.48,17.38 66.48,11.53 ; L2.1 29.21,14.39 ; 29.21,14.39 v1(29.21,15.02) ; 29.21,14.39 v1(29.21,13.63) ; J2.1 47.6,33.34 C7.1 ; D3.A v1(36.95,43.55) ; R6.1 v1(45.34,44.25) ; R17.1 v1(33.52,25.46)
  TOP w0.61: C7.1 v1(49.02,33.18)
  TOP w0.635: L1.1 v1(38.93,29.13) ; L1.1 v1(38.93,31.19) ; L1.1 v1(39.76,30.16)
  L3_PWR w0.508: D1.A 9.29,60.21 12.06,57.44 12.06,41.92 ; 72.96,68.34 D2.A ; D2.A 74.27,67.03 ; D2.A 74.27,69.65 ; 12.85,43.8 12.82,43.83
  BOTTOM w0.508: v1(26.79,30.64) 27.17,30.64 27.68,30.14 C209.1 ; v1(14.51,32.48) 13.52,32.48 C207.1 ; C214.1 14.59,24.93 v1(14.6,24.92)
  BOTTOM w0.61: R211.1 v1(17.9,33.42) ; v1(19.05,25.31) R215.1 ; R212.1 25.02,29.75 v1(24.38,29.75)
  vias: v1(66.29,10.7)
VDDA: length 20.8
  TOP w0.305: v1(17.19,21.19) 17.5,21.5 U7.31
  TOP w0.508: C18.1 14.86,18.99 ; v1(14.98,15.91) 13.84,15.91 ; v1(25.14,13.63) 25.14,14.39 ; 25.14,14.39 v1(25.14,15.02) ; 25.14,14.39 L2.2 ; v1(14.98,17.44) 13.84,17.44 ; v1(6.85,18.32) TP6.1
  TOP w0.61: C13.1 v1(17.19,21.19)
  TOP w0.889: C13.1 v1(16.18,18.99)
  BOTTOM w0.508: v1(14.98,18.96) 13.71,18.96 12.7,19.98 8.51,19.98 v1(6.85,18.32)
VIN: length 21.8
  TOP w0.508: RV200.1 65.25,30.11 R12.1
  BOTTOM w0.508: RV200.1 67.61,29.17 ; RV200.1 69.03,27.75 ; RV200.1 66.19,27.75 ; RV200.1 67.61,26.33 ; JP6.1 74.98,24.42 ; JP6.1 73.53,25.87 ; JP6.1 72.08,24.42 ; JP6.1 73.53,22.97 ; JP2.1 69.39,23.1 ; JP2.1 68.07,21.78 ; JP2.1 70.71,21.78 ; JP2.1 69.39,20.46
/PULSE_OUT: length 60.4
  TOP w0.178: R11.1 v1(78.58,34.86) ; v1(37.7,34.83) 36.7,34.83 36.31,34.44 35.04,34.44 34.03,33.44 30.48,33.44 29.96,32.91 U7.68
  BOTTOM w0.178: v1(37.7,34.83) 39.49,34.83 41.27,36.61 46.82,36.61 50.79,40.58 51.65,41.44 53.21,41.44 54.48,42.71 58.16,42.71 59.05,41.82 59.05,38.52 59.94,37.63 75.82,37.63 v1(78.58,34.86)
/RESET: length 8.8
  TOP w0.178: C12.1 30.68,27.34 30.03,27.34 29.61,26.92 U7.56 ; C12.1 R17.2 ; C12.1 31.03,27.52 31.49,27.98 34.41,27.98 R16.2
COM1: length 66.9
  TOP w0.178: v1(22.6,40.04) 22.6,39.89 23,39.49 U7.84
  L2_GND w0.178: v1(22.6,40.04) 22.6,40.68 22.61,40.69 22.61,41.06 23.57,42.02 23.57,45.68 23.57,45.68 23.57,48.1 37.28,61.82 37.28,69.57 38.13,70.41 39.38,71.66 39.38,71.66 39.79,72.08 44.47,76.76 45.36,76.76 52.25,76.76 52.29,76.8 58,76.8 58.06,76.81 DS1.23
COM2: length 68.4
  TOP w0.178: v1(23.18,40.82) 23.5,40.5 U7.83
  L2_GND w0.178: v1(23.18,40.82) 23.92,41.56 23.92,42.34 23.92,44.69 23.92,45.83 23.92,47.96 37.64,61.67 37.64,69.42 38.27,70.05 39.73,71.51 40.15,71.93 44.62,76.4 45.21,76.4 59.6,76.4 63.9,80.71 DS1.24
COM3: length 74.2
  TOP w0.178: v1(23.24,36.23) 23.36,36.23 24,36.87 U7.82
  L2_GND w0.178: DS1.25 61.29,76.05 44.77,76.05 40.5,71.78 40.09,71.37 38.42,69.7 37.99,69.27 37.99,61.53 24.28,47.81 24.28,46.56 24.28,40.06 23.24,39.02 23.24,36.23 v1(23.24,36.23)
COM4: length 76.3
  TOP w0.178: U7.81 24.5,35.86 v1(24.76,35.6)
  L2_GND w0.178: v1(24.76,35.6) 24.63,35.72 24.63,45.53 24.63,47.66 38.35,61.38 38.35,69.12 40.44,71.22 40.86,71.63 44.92,75.69 62.44,75.69 66.39,79.64 66.4,79.64 67.02,80.27 67.02,80.27 67.46,80.71 DS1.26
EEPROM_SS: length 92.2
  TOP w0.178: U7.52 29.73,24.92 30.48,24.17 34.68,24.17 35.19,24.67 37.97,24.67 40,26.71 40,28.36 43.76,32.12 44.91,32.12 55.83,32.12 58.04,34.33 58.04,40.42 61.54,43.93 61.54,52.39 61.54,52.95 61.54,56.23 68.27,62.96 68.27,65.11 65.91,67.47 62.35,67.47 61.21,68.62 56.89,68.62 55.88,69.63 55.88,72.01 57.08,73.21 U1.1
  TOP w0.508: U1.1 58.05,74.22 58.7,74.87 R1.2
FLASH_SS: length 81.8
  TOP w0.178: R2.2 59.94,66.05 59.94,66.56 60.47,67.09 65.78,67.09 67.92,64.96 67.92,63.11 61.18,56.38 61.18,55.38 61.18,53.1 61.18,52.28 61.18,44.08 57.65,40.55 57.65,34.58 55.55,32.47 45.06,32.47 43.61,32.47 39.62,28.48 39.62,26.83 37.84,25.06 35.06,25.06 34.56,24.55 30.6,24.55 29.88,25.27 29.87,25.27 29.73,25.42 U7.53
  TOP w0.508: U2.1 58.04,64.34 58.04,65.31 58.7,65.98 R2.2
I2C0_SCL: length 22.4
  TOP w0.178: 41.14,45.98 R5.2 ; U7.78 26,37.15 26.29,36.87 27.12,36.87 27.68,37.43 27.68,38.39 v1(28.19,38.9)
  TOP w0.305: v1(40.26,46.01) 41.17,46.01 ; U5.5 41.14,45.98
  BOTTOM w0.178: v1(28.19,38.9) 28.83,39.53 34.54,39.53 40.26,45.25 v1(40.26,46.01)
I2C0_SDA: length 25.8
  TOP w0.178: v1(29.71,37.37) 29.71,38.14 30.98,39.41 33.91,39.41 34.92,40.42 36.93,40.42 37.9,41.39 39.98,41.39 40.23,41.14 41.4,41.14 41.65,41.39 41.65,42.16 41.4,42.41 41.4,43.22 41.75,43.57 U5.3 ; v1(28.06,37) 27.81,37 27.33,36.51 26.01,36.51 25.5,37.01 U7.79
  TOP w0.305: U5.3 42.64,43.57 43.05,43.98 43.05,44.74 43.56,45.25 R6.2
  BOTTOM w0.178: v1(29.71,37.37) 28.95,37.37 28.58,37 v1(28.06,37)
I2C1_SCL: length 31.2
  TOP w0.178: U7.58 27.64,27.92 27.39,27.67 v1(27.28,27.67)
  BOTTOM w0.178: J200.14 31.29,49.27 R201.2 31.29,46.19 30.86,45.76 28.06,45.76 25.22,42.91 25.22,41.98 25.23,41.93 25.23,37.8 27.89,35.14 27.89,31.96 28.99,30.86 28.99,30.85 29.41,30.43 29.41,28.32 28.94,27.85 27.56,27.85 27.38,27.67 v1(27.28,27.67)
I2C1_SDA: length 35.2
  TOP w0.178: v1(27.3,26.81) 27.66,27.17 27.66,27.18 27.9,27.42 U7.57
  BOTTOM w0.178: J200.12 33.57,48.12 34.29,47.41 34.29,46.39 33.73,45.83 31.95,45.83 31.29,45.17 R202.2 30.81,45.38 28.32,45.38 25.59,42.65 25.59,37.94 28.24,35.29 28.24,32.12 29.76,30.59 29.76,28.17 29.06,27.47 28.06,27.47 27.4,26.81 v1(27.3,26.81)
KVARH_LED: length 3.9
  TOP w0.305: U7.48 26,24.35 v1(25.9,24.45)
  BOTTOM w0.508: v1(25.9,24.45) 25.9,24.04 26.67,23.28 R216.1
KWH_LED: length 3.4
  TOP w0.305: v1(30.16,26.66) 30.05,26.66 29.8,26.42 U7.55
  BOTTOM w0.508: v1(30.16,26.66) 30.33,26.83 30.35,26.83 30.98,27.47 R213.1
LCD1: length 77.1
  TOP w0.178: v1(10.54,29.09) 10.55,29.08 11.08,29.08 12.25,27.92 U7.18
  L2_GND w0.178: DS1.1 18.45,80.71 19.51,79.64 19.96,79.64 29.46,70.14 29.46,65.06 17.27,52.87 15.46,52.87 11.81,52.87 4.1,45.16 4.1,40.8 4.1,34.49 9.5,29.09 v1(10.54,29.09)
LCD2: length 75.1
  TOP w0.178: v1(9.68,29.72) 9.75,29.65 10.29,29.65 10.3,29.67 11,29.67 12.25,28.42 U7.17
  L2_GND w0.178: DS1.2 20.38,80.28 20.38,79.72 29.82,70.29 29.82,64.91 17.42,52.51 15.32,52.51 13.26,52.51 13.26,52.51 11.95,52.51 4.45,45.01 4.45,40.95 4.45,34.82 9.55,29.72 v1(9.68,29.72)
LCD3: length 73.8
  TOP w0.178: v1(10.41,30.28) 10.87,30.28 10.98,30.17 11,30.17 12.26,28.92 U7.16
  L2_GND w0.178: v1(10.41,30.28) 10.4,30.29 9.48,30.29 4.81,34.96 4.81,41.09 4.81,44.87 11.29,51.35 11.3,51.35 12.11,52.16 13.4,52.16 16.85,52.16 17.56,52.16 30.17,64.77 30.17,70.44 29.75,70.85 21.95,78.65 DS1.3
LCD4: length 72.4
  TOP w0.178: U7.15 12.26,29.42 11.14,30.53 11.13,30.53 10.8,30.85 9.81,30.85 9.81,30.86 v1(9.72,30.86)
  L2_GND w0.178: v1(9.72,30.86) 9.69,30.89 9.49,30.89 5.17,35.21 5.17,41.24 5.17,44.72 11.44,50.99 11.45,50.99 12.26,51.8 13.55,51.8 16.7,51.8 17.71,51.8 30.53,64.62 30.53,70.58 29.9,71.21 23.95,77.16 DS1.4
LCD5: length 71.1
  TOP w0.178: U7.14 12.26,29.92 11.29,30.88 11.28,30.88 10.74,31.43 v1(10.41,31.43)
  L2_GND w0.178: DS1.5 25.95,75.66 30.05,71.56 30.88,70.73 30.88,64.47 17.86,51.45 17.14,51.45 16.55,51.45 14.88,51.45 14.88,51.45 13.7,51.45 12.41,51.45 11.6,50.64 11.59,50.64 5.52,44.57 5.52,41.39 5.52,35.36 9.42,31.46 10.01,31.46 10.05,31.43 v1(10.41,31.43)
LCD6: length 69.7
  TOP w0.178: v1(9.65,32.04) 10.63,32.04 11.42,31.24 11.44,31.24 12.26,30.42 U7.13
  L2_GND w0.178: v1(9.65,32.04) 9.48,32.04 5.88,35.64 5.88,41.53 5.88,44.42 11.73,50.28 11.74,50.28 12.55,51.09 13.84,51.09 16.4,51.09 16.99,51.09 18,51.09 31.24,64.32 31.24,70.88 30.2,71.92 27.95,74.16 DS1.6
LCD7: length 68.3
  TOP w0.178: v1(10.41,32.61) 10.6,32.61 12.3,30.92 U7.12
  L2_GND w0.178: v1(10.41,32.61) 9.41,32.61 6.23,35.79 6.23,41.68 6.23,44.25 11.87,49.88 13.14,49.88 13.99,50.74 14.58,50.74 16.26,50.74 16.85,50.73 18.15,50.73 31.59,64.18 31.59,71.02 30.34,72.27 29.95,72.66 DS1.7
LCD8: length 66.5
  TOP w0.178: v1(9.64,33.19) 9.64,33.18 10.65,33.18 11.42,32.41 U7.9
  L2_GND w0.178: v1(9.64,33.19) 9.48,33.19 6.59,36.08 6.59,41.83 6.59,44.05 12.06,49.53 13.29,49.53 14.14,50.38 16.11,50.38 16.7,50.38 18.3,50.38 31.95,64.03 31.95,71.78 31.95,71.78 DS1.8
LCD9: length 66.5
  TOP w0.178: v1(10.4,33.76) 10.61,33.54 10.79,33.54 11.42,32.91 U7.8
  L2_GND w0.178: DS1.9 33.95,73.29 32.3,71.63 32.3,63.88 18.45,50.02 16.55,50.02 15.96,50.02 14.29,50.02 13.44,49.17 12.21,49.17 6.94,43.9 6.94,41.98 6.94,36.23 9.41,33.76 9.87,33.76 9.88,33.76 v1(10.4,33.76)
LCD10: length 66.4
  TOP w0.178: U7.7 11.55,33.41 10.64,34.33 10.03,34.33 10.03,34.33 v1(9.65,34.33)
  L2_GND w0.178: DS1.10 35.95,74.77 32.66,71.48 32.66,63.73 18.59,49.67 16.4,49.67 15.82,49.67 14.43,49.67 13.58,48.82 12.36,48.82 7.3,43.76 7.3,42.12 7.3,36.56 9.53,34.33 v1(9.65,34.33)
LCD11: length 66.5
  TOP w0.178: v1(10.41,34.9) 10.57,34.9 11.55,33.91 U7.6
  L2_GND w0.178: DS1.11 37.95,76.27 33.02,71.33 33.02,63.59 18.74,49.31 16.26,49.31 15.67,49.31 14.58,49.31 13.73,48.46 13.26,48.46 12.51,48.46 7.65,43.61 7.65,42.27 7.65,36.71 9.46,34.9 9.88,34.9 9.89,34.9 v1(10.41,34.9)
LCD12: length 66.4
  TOP w0.178: U7.5 11.7,34.41 10.65,35.47 9.78,35.47 9.65,35.6 v1(9.57,35.6)
  L2_GND w0.178: DS1.12 39.84,80.55 39.84,77.65 33.37,71.19 33.37,63.44 18.89,48.96 16.11,48.96 15.52,48.96 14.73,48.96 13.88,48.11 12.65,48.11 8.01,43.46 8.01,42.42 8.01,37.06 9.26,35.81 9.36,35.81 v1(9.57,35.6)
LCD13: length 66.4
  TOP w0.178: U7.4 11.7,34.91 10.79,35.83 10.63,35.83 v1(10.34,36.11)
  L2_GND w0.178: DS1.13 41.95,79.27 33.94,71.25 33.73,71.04 33.73,63.29 19.04,48.6 15.96,48.6 15.37,48.6 14.88,48.6 14.02,47.75 13.44,47.75 12.8,47.75 8.37,43.32 8.37,42.57 8.37,42.57 8.37,37.21 9.4,36.17 9.81,36.17 9.86,36.11 v1(10.34,36.11)
LCD14: length 66.4
  TOP w0.178: U7.3 11.85,35.41 11.23,36.04 11.22,36.04 10.58,36.69 9.69,36.69 v1(9.64,36.74)
  L2_GND w0.178: DS1.14 43.2,79.96 43.15,79.96 36.8,73.61 35.9,72.71 34.08,70.89 34.08,63.15 19.18,48.25 15.82,48.25 15.02,48.25 14.17,47.39 12.95,47.39 8.72,43.17 8.72,37.5 9.48,36.74 v1(9.64,36.74)
LCD15: length 67.3
  TOP w0.178: v1(10.38,37.26) 10.53,37.26 11.87,35.91 U7.2
  L2_GND w0.178: DS1.15 44.85,79.6 43.3,79.6 36.95,73.25 36.63,72.94 34.44,70.74 34.44,63 19.33,47.89 15.67,47.89 15.17,47.89 14.32,47.04 13.09,47.04 9.08,43.02 9.08,37.65 9.41,37.31 9.88,37.31 9.93,37.26 v1(10.38,37.26)
LCD16: length 67.9
  TOP w0.178: U7.1 12,36.41 10.95,37.47 10.95,37.49 10.62,37.83 9.7,37.83 v1(9.65,37.88)
  L2_GND w0.178: v1(9.65,37.88) 9.65,43.09 13.24,46.68 14.47,46.68 15.32,47.53 19.48,47.53 34.79,62.85 34.79,70.6 37.1,72.9 43.44,79.25 46.49,79.25 DS1.16
LCD17: length 63.4
  TOP w0.178: v1(15.13,46.49) 15.49,46.14 15.49,42.05 16.93,40.61 17.5,40.61 18,40.12 U7.94
  L2_GND w0.178: v1(15.13,46.49) 15.82,47.18 19.62,47.18 35.15,62.7 35.15,70.45 37.66,72.96 43.59,78.89 46.24,78.89 48.14,78.89 DS1.17
LCD18: length 64.4
  TOP w0.178: v1(16.25,46.52) 15.87,46.14 15.87,42.23 17.14,40.97 17.65,40.97 18.5,40.12 U7.93
  L2_GND w0.178: DS1.18 51.95,80.53 49.96,78.54 48.94,78.54 43.74,78.54 38.02,72.81 37.39,72.19 35.51,70.3 35.51,62.56 19.77,46.82 16.56,46.82 v1(16.25,46.52)
LCD19: length 61.1
  TOP w0.178: v1(20.79,42.72) 20.79,42.6 20.38,42.2 20.38,39.85 21,39.23 U7.88
  L2_GND w0.178: v1(20.79,42.72) 20.79,45.34 22.14,46.7 22.14,47.89 22.14,48.31 22.14,48.69 35.86,62.41 35.86,70.16 37.54,71.83 37.95,72.25 38.37,72.67 43.89,78.18 45.95,78.18 50.56,78.18 51.37,78.18 51.41,78.22 51.46,78.22 DS1.19
LCD20: length 67.3
  TOP w0.178: v1(20.32,36.23) 20.44,36.23 20.95,36.23 21.5,36.78 U7.87
  L2_GND w0.178: v1(20.32,36.23) 20.32,36.23 20.32,39.41 21.88,40.97 21.88,43.34 22.5,43.96 22.5,46.96 22.5,48.55 36.22,62.26 36.22,70.01 37.68,71.48 38.31,72.1 38.73,72.52 44.03,77.82 45.8,77.82 50.42,77.82 51.52,77.82 51.56,77.86 52.73,77.86 53.11,77.86 DS1.20
LCD21: length 63.6
  TOP w0.178: U7.86 22,40.28 22.48,40.75 v1(22.48,42.45)
  L2_GND w0.178: v1(22.48,42.45) 22.48,43.38 22.86,43.76 22.86,46.5 22.86,48.4 36.57,62.11 36.57,69.86 37.83,71.12 39.08,72.37 44.18,77.47 45.65,77.47 50.27,77.47 51.83,77.47 51.87,77.51 52.58,77.51 54.75,77.51 DS1.21
LCD22: length 69.4
  TOP w0.178: v1(21.97,36.23) 22.5,36.77 U7.85
  L2_GND w0.178: v1(21.97,36.23) 21.97,40.55 22.25,40.84 22.25,41.22 22.78,41.75 22.79,41.75 23.21,42.17 23.21,46.12 23.21,46.12 23.21,47.63 23.21,48.25 36.93,61.97 36.93,69.71 37.98,70.77 39.02,71.81 39.44,72.22 39.44,72.22 44.33,77.11 45.51,77.11 50.12,77.11 51.98,77.11 52.02,77.15 56.4,77.15 DS1.22
MMA_EN: length 21.1
  TOP w0.178: U5.4 41.64,44.22 40.06,42.64 40.06,42 39.87,41.82 37.83,41.82 36.81,40.8 34.79,40.8 34.54,40.55 v1(34.03,40.55) ; U7.80 25,39.39 25.27,39.66 26.03,39.66 v1(26.54,40.17)
  BOTTOM w0.178: v1(26.54,40.17) 26.79,39.91 33.4,39.91 v1(34.03,40.55)
MMA_XOUT: length 13.8
  TOP w0.178: U5.10 37.77,42.27 36.69,41.18 33.78,41.18 32.38,39.79 30.86,39.79 28.75,37.68 U7.75
MMA_YOUT: length 14.9
  TOP w0.178: U7.76 27,39.11 28.06,40.17 32.25,40.17 33.65,41.57 36.57,41.57 37.92,42.92 U5.9
MMA_ZOUT: length 15.8
  TOP w0.178: U7.77 26.5,39.32 27.73,40.55 32,40.55 33.4,41.95 36.45,41.95 37.06,42.56 38.07,43.57 U5.8
PWR_MSR: length 17
  TOP w0.305: v1(23.62,24.42) 23.62,24.41 23.98,24.04 23.98,22.68 U7.44
  TOP w0.508: v1(23.62,24.42) 22.86,25.18 22.86,28.61 21.74,29.73 21.74,30.95 22.32,31.53 24.51,31.53 25.4,30.64 v1(25.52,30.64)
  BOTTOM w0.508: R206.1 R207.2
  BOTTOM w0.61: C211.1 v1(23.62,24.42) ; R207.2 v1(25.52,30.64)
RES_INP: length 4
  TOP w0.178: R20.1 19.68,12.23 J7.2
RES_OUT: length 4
  TOP w0.178: R19.1 17.9,11.97 J7.1
RF_CTRL: length 21.7
  TOP w0.178: v1(26.51,34.75) 26.51,34.68 26.48,34.64 26.48,33.37 27.39,32.46 27.39,31.36 27.83,30.92 U7.64
  BOTTOM w0.178: J200.18 26.54,48.94 26.54,44.75 24.86,43.07 24.86,37.16 26.29,35.74 26.29,34.97 v1(26.51,34.75)
RF_IO: length 45.3
  TOP w0.178: U7.23 12.4,25.42 12.22,25.59 v1(11.93,25.59)
  BOTTOM w0.178: J200.17 25.95,55.87 24.76,57.06 22.48,57.06 20.44,55.03 20.44,47.65 18.31,45.51 16.98,45.51 16.34,44.87 16.34,43.93 14.87,42.45 13.46,42.45 12.32,41.31 12.32,34.82 11.41,33.92 10.99,33.5 10.99,32.91 10.99,30.07 12.06,29.01 12.06,28.28 11.36,27.58 11.36,26.22 11.93,25.64 v1(11.93,25.59)
RF_RST: length 35.3
  TOP w0.178: v1(25.84,46.26) 26.48,45.62 30.8,45.62 31.75,46.58 31.75,48.04 33.65,49.94 33.65,50.2 36.04,52.59 v1(36.11,52.59) ; v1(25.65,35.09) 25.94,34.8 25.94,34.51 26.09,34.35 26.09,33.25 27.03,32.32 27.03,31.22 27.83,30.42 U7.63
  BOTTOM w0.178: J200.9 v1(36.11,52.59) ; v1(25.65,35.09) 25.65,35.87 24.51,37.01 24.51,43.22 25.84,44.55 v1(25.84,46.26)
SAR_VDDA: length 11.7
  TOP w0.305: 30.26,29.4 30.24,29.42 U7.61
  TOP w0.508: 36.55,29.4 37.59,28.36 TP1.1
  TOP w0.889: 30.26,29.4 C8.1 C9.1 C10.1 C11.1 36.6,29.4 37.11,29.92 L1.2
SCI0_RX: length 47.6
  TOP w0.178: R9.1 C6.1 v1(49.96,37.55) ; U7.47 25.5,21.77 25.9,21.37 27.17,21.37 27.56,21.75 27.56,22.39 27.94,22.77 28.7,22.77 30.48,20.99 32.88,20.99 34.79,19.09 43.43,19.09 47.24,22.9 47.24,29.85 47.65,30.26 49.65,30.26 v1(50.16,29.75)
  BOTTOM w0.178: v1(50.16,29.75) 50.16,37.35 v1(49.96,37.55)
SCI0_TX: length 47.5
  TOP w0.178: U7.46 25,24.41 25.61,25.02 26.14,25.02 27.05,24.11 27.41,24.11 27.7,24.11 27.82,24 29.64,24 30.23,23.4 34.92,23.4 35.43,23.91 45.84,23.91 46.17,24.24 46.17,30.29 47.29,31.41 56.13,31.41 59.23,34.5 R10.1
SCI1_RX: length 17.7
  TOP w0.178: v1(10.41,38.52) 10.66,38.52 12.06,37.12 13.97,37.12 14.71,36.38 14.71,36.1 15.25,35.56 18.5,35.56 19.39,36.45 19.39,36.62 19.5,36.73 U7.91 ; v1(10.41,39.66) 10.16,39.66 9.7,40.12 R8.2 U3.3
  BOTTOM w0.178: v1(10.41,39.66) v1(10.41,38.52)
SCI1_TX: length 16
  TOP w0.178: R7.1 7.72,41.46 10.09,39.09 10.73,39.09 12.34,37.48 14.11,37.48 15.07,36.52 15.07,36.25 15.4,35.91 18.3,35.91 19,36.61 U7.92
SCI3_CTS: length 44.1
  TOP w0.178: v1(11.93,27.34) 11.93,27.26 12.28,26.92 U7.20
  BOTTOM w0.178: J200.13 31.03,53.68 30.1,52.74 22.09,52.74 20.82,51.47 20.82,47.49 18.46,45.13 17.1,45.13 16.7,44.72 16.7,43.78 15.02,42.1 13.61,42.1 12.7,41.19 12.7,34.7 11.35,33.35 11.35,30.22 12.44,29.13 12.44,27.85 v1(11.93,27.34)
SCI3_RTS: length 47
  TOP w0.178: v1(14.51,27.47) 14.21,27.47 14.15,27.42 U7.19
  BOTTOM w0.178: J200.11 33.57,53.68 32.28,52.39 22.25,52.39 21.21,51.34 21.21,47.3 18.67,44.76 17.55,44.76 17.14,44.36 17.14,43.72 15.17,41.74 13.75,41.74 13.08,41.07 13.08,34.58 11.71,33.2 11.71,30.37 12.82,29.25 12.82,27.72 13.08,27.47 v1(14.51,27.47)
SCI3_RX: length 53.5
  TOP w0.178: U7.22 14.5,25.92 v1(14.52,25.89)
  BOTTOM w0.178: v1(14.52,25.89) 14.88,25.89 15.49,26.5 15.49,28.23 15.11,28.61 13.97,28.61 13.59,28.99 13.59,29.5 12.44,30.64 12.44,32.93 14.09,34.58 15.12,34.58 15.2,34.5 17.7,34.5 18.67,35.47 18.67,43.35 19.46,44.14 19.46,44.4 21.97,46.91 21.97,50.96 22.6,51.6 37.72,51.6 38.65,50.66 J200.8
SCI3_TX: length 55.1
  TOP w0.178: v1(14.87,26.68) 14.49,26.68 14.23,26.42 U7.21
  BOTTOM w0.178: J200.6 41.19,50.53 39.71,52.02 22.51,52.02 21.59,51.09 21.59,47.16 18.82,44.4 17.94,44.4 17.65,44.11 17.65,43.72 15.31,41.39 13.9,41.39 13.48,40.97 13.48,34.48 12.06,33.06 12.06,30.52 13.2,29.37 13.2,28.74 13.71,28.23 14.86,28.23 15.11,27.98 15.11,26.96 14.87,26.72 v1(14.87,26.68)
SDADM0: length 6.6
  TOP w0.178: R20.2 19.68,17.69 20.32,18.32 20.32,19.72 19.66,20.38 C17.1 19.4,20.38 19,20.78 U7.34
SDADM2: length 5.5
  TOP w0.178: U7.40 22,21.59 22.98,20.61 C15.1 25.24,20.61 R18.1
SDADP0: length 6.7
  TOP w0.178: U7.33 18.5,20.83 18.06,20.38 C16.1 17.8,20.38 17.01,19.59 17.01,18.45 17.9,17.56 R19.2
SDADP2: length 38.4
  TOP w0.178: U7.39 21.5,20.69 C14.1 21.84,20.61 22.48,19.98 22.48,17.36 R21.1 23.67,18.2 28.06,18.2 30.48,20.61 32.76,20.61 34.67,18.71 43.81,18.71 47.75,22.64 47.75,24.95 R13.2
SPI0_MISO: length 84.9
  TOP w0.178: U7.51 29.72,24.42 30.35,23.79 34.8,23.79 35.31,24.29 38.1,24.29 40.38,26.58 40.38,28.23 43.91,31.76 44.77,31.76 55.98,31.76 58.42,34.2 58.42,40.3 61.9,43.78 61.9,52.81 61.9,56.08 68.63,62.82 68.63,65.26 66.06,67.83 62.5,67.83 61.74,68.59 61.74,70.37 60.17,71.94 U1.2
SPI0_MOSI: length 91.2
  TOP w0.178: U7.50 27.49,23.15 28.83,23.15 30.6,21.37 33.01,21.37 34.91,19.47 43.18,19.47 46.88,23.18 46.88,30 47.53,30.64 56.38,30.64 60.19,34.45 63.5,34.45 64.42,35.38 64.42,42.04 62.61,43.85 62.61,55.79 69.34,62.52 69.34,63.11 69.34,65.55 68.64,66.25 66.98,67.92 66.98,67.93 66.29,68.62 63.75,68.62 63.45,68.91 U1.5
SPI0_SCK: length 92.4
  TOP w0.178: U1.6 62.53,70.67 62.1,70.24 62.1,68.73 62.65,68.18 66.2,68.18 66.62,67.77 68.98,65.41 68.98,62.67 62.25,55.94 62.25,52.66 62.25,43.7 64.07,41.88 64.07,35.52 63.39,34.85 60.08,34.85 56.28,31.05 47.43,31.05 46.53,30.15 46.53,23.96 46.1,23.53 35.56,23.53 35.07,23.05 30.08,23.05 29.6,23.53 27.56,23.53 27.33,23.76 26.64,23.76 26.5,23.62 U7.49
SPI1_MISO: length 52.1
  TOP w0.178: U2.2 v1(56.74,63.05) ; U7.72 33.1,34.91 35.62,37.44 v1(35.62,37.95)
  BOTTOM w0.178: v1(35.62,37.95) 36.14,37.95 38.34,40.14 46.83,40.14 50.64,43.95 52.17,43.95 54.48,46.26 54.48,53.63 55.77,54.93 J201.2 58.02,57.19 56.74,58.47 v1(56.74,63.05)
SPI1_MOSI: length 51.5
  TOP w0.178: v1(34.79,37.5) 34.79,37.12 33.09,35.41 U7.73 ; U2.5 v1(62.22,60.51)
  BOTTOM w0.178: v1(34.79,37.5) 34.92,37.37 36.07,37.37 37.59,38.9 46.09,38.9 50.79,43.6 52.32,43.6 54.83,46.12 54.83,51.32 55.9,52.39 J201.4 59.2,52.39 60.32,53.5 60.32,56.55 62.22,58.45 v1(62.22,60.51)
SPI1_SCK: length 54.3
  TOP w0.178: U7.71 29.95,34.41 30.04,34.5 33.19,34.5 34.29,35.6 34.67,35.6 v1(34.79,35.72) ; U2.6 v1(64.77,61.78)
  BOTTOM w0.178: v1(64.77,61.78) 64.77,60.36 60.7,56.3 60.7,51.34 59.2,49.85 J201.6 55.9,49.85 55.19,49.13 55.19,48.19 55.19,45.97 52.46,43.24 51.62,43.24 50.94,43.24 46.21,38.52 37.72,38.52 35.05,35.85 34.92,35.85 v1(34.79,35.72)
SWD_CLK: length 13.6
  TOP w0.178: U7.66 28.75,31.91 29.97,31.91 30.78,32.73 34.46,32.73 35.47,33.73 37.9,33.73 38.78,34.61 J2.4
SWD_IO: length 13.3
  TOP w0.178: J2.2 35.71,33.34 34.74,32.37 30.93,32.37 29.96,31.41 28.76,31.41 U7.65
SWD_RESET: length 20.2
  TOP w0.178: R16.1 35.43,25.44 37.72,25.44 39.24,26.96 39.24,28.61 43.14,32.51 43.14,38.19 42.91,38.42 J2.10
TAMPER1: length 12.3
  TOP w0.178: v1(16.38,29.93) 17.14,29.17 17.14,25.31 16.89,25.06 16.89,24.17 16.5,23.78 U7.29
  BOTTOM w0.178: R210.1 19.17,31.41 18.28,31.41 R211.2 16.38,31.02 v1(16.38,29.93)
TAMPER2: length 8.4
  TOP w0.178: U7.28 16,23.99 16.38,24.36 16.38,25.44 16.51,25.56 v1(16.51,26.83)
  BOTTOM w0.178: R214.1 18.79,26.83 R215.2 v1(16.51,26.83) 16.38,26.71 16.38,25.79 C215.1
UMI_INT: length 40.5
  TOP w0.178: v1(38.35,36.61) 38.35,34.68 37.76,34.09 35.31,34.09 34.31,33.08 30.63,33.08 29.96,32.41 U7.67
  BOTTOM w0.178: J201.9 61.74,44.77 60.45,43.47 54.23,43.47 52.9,42.15 51.35,42.15 50.91,41.7 46.58,37.37 39.11,37.37 v1(38.35,36.61)
UMI_RST: length 34.4
  TOP w0.178: U7.69 29.96,33.41 30.34,33.79 33.75,33.79 34.76,34.8 36.07,34.8 36.57,35.3 36.57,35.78 v1(36.66,35.87)
  BOTTOM w0.178: J201.10 56.79,44.77 55.88,43.85 54.1,43.85 52.78,42.53 51.91,42.53 51.23,42.53 46.46,37.76 38.35,37.76 36.66,36.07 v1(36.66,35.87)
UMI_SS: length 35.6
  TOP w0.178: v1(35.81,35.72) 35.81,35.67 35.29,35.15 34.48,35.15 33.47,34.15 30.19,34.15 29.95,33.91 U7.70
  BOTTOM w0.178: J201.8 55.9,47.31 55.55,46.95 55.55,45.82 52.61,42.89 51.47,42.89 51.09,42.89 46.34,38.14 38.1,38.14 35.81,35.85 v1(35.81,35.72)
USER_BTN: length 30.9
  TOP w0.178: v1(27.31,25.94) 27.65,25.94 27.68,25.92 U7.54
  BOTTOM w0.178: 26.79,29.5 26.79,29.36 25.32,27.89 25.32,26.41 25.66,26.07 C210.1 26.29,25.94 v1(27.31,25.94) 28.45,27.09 29.19,27.09 30.02,27.92 30.12,28.02 30.12,30.75 28.6,32.27 28.6,35.44 25.97,38.07 25.97,41.51 26.79,42.34 28.43,42.34 29.33,41.44 R203.1
USER_LED: length 5.1
  TOP w0.178: v1(19.74,41.42) 19.74,39.48 20,39.21 U7.90
  BOTTOM w0.178: v1(19.74,41.42) 19.74,40.19 R204.1
VAUX: length 106.4
  TOP w0.305: 31.75,36.23 31.43,35.91 U7.74
  TOP w0.508: 31.75,36.23 v1(33.14,37.63) v1(33.65,38.14) 33.65,38.26 34.92,39.53 41.91,39.53 42.93,40.56 46.59,40.56 47.75,39.41 47.75,36.71 48.74,35.72 50.16,35.72 51.05,34.83 v1(56.31,34.83) ; R1.1 62.84,74.87 63.45,74.25 U1.8 C1.1 ; U1.3 v1(56.51,70.67) ; C1.1 v1(65.32,74.53) ; C1.1 65.32,72.22 65.05,71.94 U1.7
  BOTTOM w0.508: v1(33.14,37.63) v1(33.65,38.14) 33.78,38.26 34.79,38.26 35.3,38.77 35.94,38.77 37.97,40.8 46.73,40.8 51.81,45.88 51.81,65.31 56.51,70.01 v1(56.51,70.67) 56.51,73.06 57.98,74.53 v1(65.32,74.53) ; R205.1 v1(56.31,34.83)
VCAP1: length 1.7
  TOP w0.305: U7.100 v1(14.35,38.16)
  BOTTOM w0.508: v1(14.35,38.16) 14.35,38.24 14.32,38.26 14.32,39.12 C202.1
VCAP2: length 3.6
  TOP w0.305: v1(15.36,40.68) 15.36,39.66 15.5,39.52 U7.99
  BOTTOM w0.508: v1(15.36,40.68) C202.2
VLL1: length 2.8
  TOP w0.305: U7.98 16,39.54 v1(16.25,39.79)
  BOTTOM w0.61: v1(16.25,39.79) 15.74,39.28 C204.1
VLL2: length 3
  TOP w0.305: U7.97 v1(16.5,36.49)
  BOTTOM w0.61: v1(16.5,36.49) 16.5,36.29 17.01,35.77 C205.1
VLL3: length 2.6
  TOP w0.305: v1(17.27,39.78) 17,39.51 U7.96
  BOTTOM w0.61: C203.1 v1(17.27,39.78)
VOUT: length 5.3
  BOTTOM w0.508: JP1.1 37.38,23.1 ; JP1.1 36.06,21.78 ; JP1.1 38.71,21.78 ; JP1.1 37.38,20.46
  vias: v1(41.4,15.4) v1(42.54,15.4)
VPWR: length 224.2
  TOP w0.508: U4.1 3.19,42.63 3.19,41.78 3.38,41.59 v1(3.38,40.92) ; 51.69,19.21 55.5,19.21 57.53,21.25 57.53,22.9 58.67,24.04 67.81,24.04 77.26,33.49 U6.1 75.44,39.91 73.27,39.91 67.15,46.04 v1(67.15,53.53) ; 51.69,19.21 51.69,9.38 51.33,9.03 ; 51.69,19.21 TP2.1 50.42,23.02 v1(50.42,26.58) ; 11.55,41.13 v1(11.55,40.3) ; 11.55,41.13 11.6,41.18 13.71,41.18 14.6,42.07 14.6,44.61 14.22,44.99 14.22,48.8 15.49,50.07 22.65,50.07 23.49,49.23 23.49,45.88 24.51,44.87 v1(25.27,44.87) 25.29,44.89 v1(33.69,44.89) v1(33.69,46.67) 34.3,47.28 v1(46.27,47.28) 46.35,47.28 48.76,44.87 48.76,37.12 v1(49.02,36.87) ; 11.55,41.13 R8.1 ; U2.8 63.45,65.36 63.37,65.31 62.84,65.98 R2.1 ; U2.8 63.05,63.92 61.72,63.92 59.58,61.78 U2.3 ; U2.8 C2.1 ; C2.1 65.45,63.46 65.05,63.05 U2.7 ; C2.1 v1(65.45,65.33)
  TOP w0.762: R23.1 47.86,9.01 U8.5
  TOP w0.889: D6.2 51.77,9.07 C26.1 C25.1 48,9.03 R23.1
  BOTTOM w0.508: v1(67.15,53.53) 67.59,53.53 68.7,54.65 68.7,56.68 66.16,59.22 66.16,64.62 v1(65.45,65.33) ; v1(3.38,40.92) 10.8,40.92 11.43,40.3 v1(11.55,40.3) ; v1(25.27,44.87) 25.27,44.71 23.99,43.43 23.99,42.06 23.99,41.85 23.99,35.33 24.86,34.45 25.27,34.45 25.52,34.2 v1(25.52,34.06) ; C201.1 44.9,47.08 46.07,47.08 v1(46.27,47.28) J200.2 ; J201.1 63.1,55.05 C200.1 R200.1 ; v1(49.02,36.87) 49.02,36.49 46.48,33.95 46.48,30.52 v1(50.42,26.58)
  BOTTOM w0.61: v1(25.52,34.06) R207.1 ; R200.1 v1(67.15,53.53) ; R201.1 v1(33.69,46.67) ; R202.1 v1(33.69,44.89)
